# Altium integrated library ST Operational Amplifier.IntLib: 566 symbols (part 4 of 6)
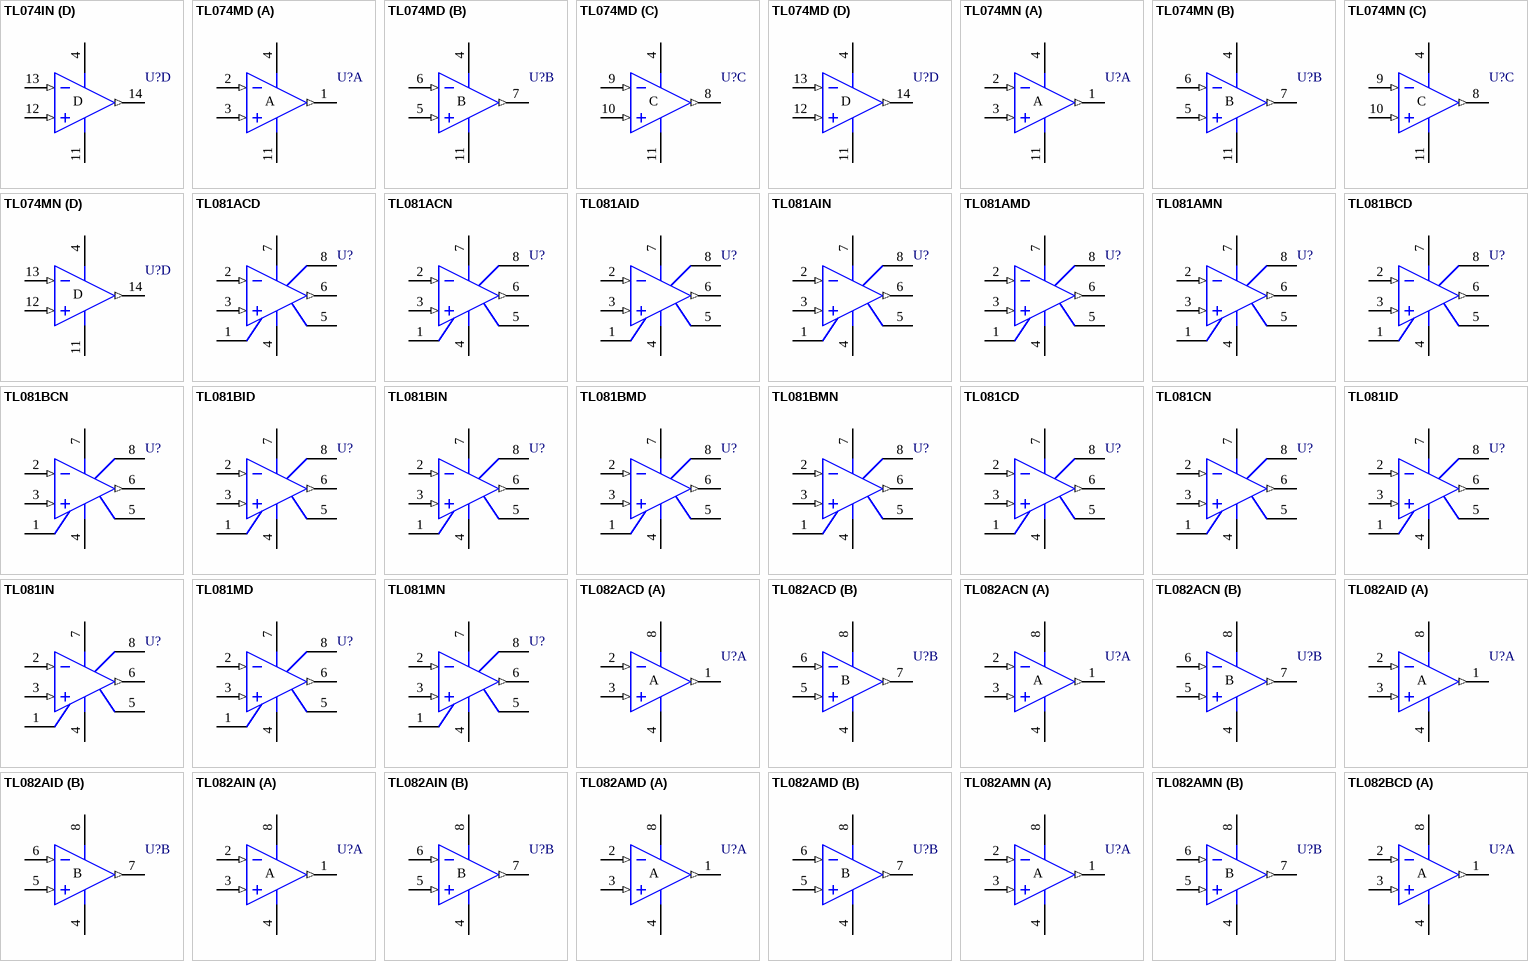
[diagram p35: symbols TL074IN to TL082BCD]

## TL074IN
designator U?
Low-Noise J-FET Quad Operational Amplifier
footprint DIP14 (DIP; 14 Leads; Row Spacing 7.62 mm; Pitch 2.54 mm)
3D model DIP14 (DIP; 14 Leads; Row Spacing 7.62 mm; Pitch 2.54 mm)
simulation model TL074 (SUBCKT)
pins on every part: 4 V+ (power), 11 V- (power)
part A pins: 1 OUT (out), 2 IN- (in), 3 IN+ (in)
part B pins: 5 IN+ (in), 6 IN- (in), 7 OUT (out)
part C pins: 8 OUT (out), 9 IN- (in), 10 IN+ (in)
part D pins: 12 IN+ (in), 13 IN- (in), 14 OUT (out)

## TL074MD
designator U?
Low-Noise J-FET Quad Operational Amplifier
footprint SO14_N (SOIC, 14-Leads, Body 8.7x3.9mm, Pitch 1.27mm, IPC Medium Density)
footprint SO14_L (SOIC, 14-Leads, Body 8.7x3.9mm, Pitch 1.27mm, IPC High Density)
footprint SO14_M (SOIC, 14-Leads, Body 8.7x3.9mm, Pitch 1.27mm, IPC Low Density)
3D model SO14 (14-Pin Small Outline Integrated Circuit 1.27 mm Pitch)
simulation model TL074 (SUBCKT)
pins on every part: 4 V+ (power), 11 V- (power)
part A pins: 1 OUT (out), 2 IN- (in), 3 IN+ (in)
part B pins: 5 IN+ (in), 6 IN- (in), 7 OUT (out)
part C pins: 8 OUT (out), 9 IN- (in), 10 IN+ (in)
part D pins: 12 IN+ (in), 13 IN- (in), 14 OUT (out)

## TL074MN
designator U?
Low-Noise J-FET Quad Operational Amplifier
footprint DIP14 (DIP; 14 Leads; Row Spacing 7.62 mm; Pitch 2.54 mm)
3D model DIP14 (DIP; 14 Leads; Row Spacing 7.62 mm; Pitch 2.54 mm)
simulation model TL074 (SUBCKT)
pins on every part: 4 V+ (power), 11 V- (power)
part A pins: 1 OUT (out), 2 IN- (in), 3 IN+ (in)
part B pins: 5 IN+ (in), 6 IN- (in), 7 OUT (out)
part C pins: 8 OUT (out), 9 IN- (in), 10 IN+ (in)
part D pins: 12 IN+ (in), 13 IN- (in), 14 OUT (out)

## TL081ACD
designator U?
General-Purpose J-FET Single Operational Amplifier
footprint SO8_N (SOIC, 8-Leads, Body 4.9x3.9mm, Pitch 1.27mm, IPC Medium Density)
footprint SO8_L (SOIC, 8-Leads, Body 4.9x3.9mm, Pitch 1.27mm, IPC High Density)
footprint SO8_M (SOIC, 8-Leads, Body 4.9x3.9mm, Pitch 1.27mm, IPC Low Density)
3D model SO8 (8-Pin Small Outline Integrated Circuit 1.27 mm Pitch)
simulation model TL081 (SUBCKT)
pins: 1 OS NULL, 2 IN- (in), 3 IN+ (in), 4 V- (power), 5 OS NULL, 6 OUT (out), 7 V+ (power), 8 NC

## TL081ACN
designator U?
General-Purpose J-FET Single Operational Amplifier
footprint DIP8 (DIP; 8 Leads; Row Spacing 7.62 mm; Pitch 2.54 mm)
3D model DIP8 (DIP; 8 Leads; Row Spacing 7.62 mm; Pitch 2.54 mm)
simulation model TL081 (SUBCKT)
pins: 1 OS NULL, 2 IN- (in), 3 IN+ (in), 4 V- (power), 5 OS NULL, 6 OUT (out), 7 V+ (power), 8 NC

## TL081AID
designator U?
General-Purpose J-FET Single Operational Amplifier
footprint SO8_N (SOIC, 8-Leads, Body 4.9x3.9mm, Pitch 1.27mm, IPC Medium Density)
footprint SO8_L (SOIC, 8-Leads, Body 4.9x3.9mm, Pitch 1.27mm, IPC High Density)
footprint SO8_M (SOIC, 8-Leads, Body 4.9x3.9mm, Pitch 1.27mm, IPC Low Density)
3D model SO8 (8-Pin Small Outline Integrated Circuit 1.27 mm Pitch)
simulation model TL081 (SUBCKT)
pins: 1 OS NULL, 2 IN- (in), 3 IN+ (in), 4 V- (power), 5 OS NULL, 6 OUT (out), 7 V+ (power), 8 NC

## TL081AIN
designator U?
General-Purpose J-FET Single Operational Amplifier
footprint DIP8 (DIP; 8 Leads; Row Spacing 7.62 mm; Pitch 2.54 mm)
3D model DIP8 (DIP; 8 Leads; Row Spacing 7.62 mm; Pitch 2.54 mm)
simulation model TL081 (SUBCKT)
pins: 1 OS NULL, 2 IN- (in), 3 IN+ (in), 4 V- (power), 5 OS NULL, 6 OUT (out), 7 V+ (power), 8 NC

## TL081AMD
designator U?
General-Purpose J-FET Single Operational Amplifier
footprint SO8_N (SOIC, 8-Leads, Body 4.9x3.9mm, Pitch 1.27mm, IPC Medium Density)
footprint SO8_L (SOIC, 8-Leads, Body 4.9x3.9mm, Pitch 1.27mm, IPC High Density)
footprint SO8_M (SOIC, 8-Leads, Body 4.9x3.9mm, Pitch 1.27mm, IPC Low Density)
3D model SO8 (8-Pin Small Outline Integrated Circuit 1.27 mm Pitch)
simulation model TL081 (SUBCKT)
pins: 1 OS NULL, 2 IN- (in), 3 IN+ (in), 4 V- (power), 5 OS NULL, 6 OUT (out), 7 V+ (power), 8 NC

## TL081AMN
designator U?
General-Purpose J-FET Single Operational Amplifier
footprint DIP8 (DIP; 8 Leads; Row Spacing 7.62 mm; Pitch 2.54 mm)
3D model DIP8 (DIP; 8 Leads; Row Spacing 7.62 mm; Pitch 2.54 mm)
simulation model TL081 (SUBCKT)
pins: 1 OS NULL, 2 IN- (in), 3 IN+ (in), 4 V- (power), 5 OS NULL, 6 OUT (out), 7 V+ (power), 8 NC

## TL081BCD
designator U?
General-Purpose J-FET Single Operational Amplifier
footprint SO8_N (SOIC, 8-Leads, Body 4.9x3.9mm, Pitch 1.27mm, IPC Medium Density)
footprint SO8_L (SOIC, 8-Leads, Body 4.9x3.9mm, Pitch 1.27mm, IPC High Density)
footprint SO8_M (SOIC, 8-Leads, Body 4.9x3.9mm, Pitch 1.27mm, IPC Low Density)
3D model SO8 (8-Pin Small Outline Integrated Circuit 1.27 mm Pitch)
simulation model TL081 (SUBCKT)
pins: 1 OS NULL, 2 IN- (in), 3 IN+ (in), 4 V- (power), 5 OS NULL, 6 OUT (out), 7 V+ (power), 8 NC

## TL081BCN
designator U?
General-Purpose J-FET Single Operational Amplifier
footprint DIP8 (DIP; 8 Leads; Row Spacing 7.62 mm; Pitch 2.54 mm)
3D model DIP8 (DIP; 8 Leads; Row Spacing 7.62 mm; Pitch 2.54 mm)
simulation model TL081 (SUBCKT)
pins: 1 OS NULL, 2 IN- (in), 3 IN+ (in), 4 V- (power), 5 OS NULL, 6 OUT (out), 7 V+ (power), 8 NC

## TL081BID
designator U?
General-Purpose J-FET Single Operational Amplifier
footprint SO8_N (SOIC, 8-Leads, Body 4.9x3.9mm, Pitch 1.27mm, IPC Medium Density)
footprint SO8_L (SOIC, 8-Leads, Body 4.9x3.9mm, Pitch 1.27mm, IPC High Density)
footprint SO8_M (SOIC, 8-Leads, Body 4.9x3.9mm, Pitch 1.27mm, IPC Low Density)
3D model SO8 (8-Pin Small Outline Integrated Circuit 1.27 mm Pitch)
simulation model TL081 (SUBCKT)
pins: 1 OS NULL, 2 IN- (in), 3 IN+ (in), 4 V- (power), 5 OS NULL, 6 OUT (out), 7 V+ (power), 8 NC

## TL081BIN
designator U?
General-Purpose J-FET Single Operational Amplifier
footprint DIP8 (DIP; 8 Leads; Row Spacing 7.62 mm; Pitch 2.54 mm)
3D model DIP8 (DIP; 8 Leads; Row Spacing 7.62 mm; Pitch 2.54 mm)
simulation model TL081 (SUBCKT)
pins: 1 OS NULL, 2 IN- (in), 3 IN+ (in), 4 V- (power), 5 OS NULL, 6 OUT (out), 7 V+ (power), 8 NC

## TL081BMD
designator U?
General-Purpose J-FET Single Operational Amplifier
footprint SO8_N (SOIC, 8-Leads, Body 4.9x3.9mm, Pitch 1.27mm, IPC Medium Density)
footprint SO8_L (SOIC, 8-Leads, Body 4.9x3.9mm, Pitch 1.27mm, IPC High Density)
footprint SO8_M (SOIC, 8-Leads, Body 4.9x3.9mm, Pitch 1.27mm, IPC Low Density)
3D model SO8 (8-Pin Small Outline Integrated Circuit 1.27 mm Pitch)
simulation model TL081 (SUBCKT)
pins: 1 OS NULL, 2 IN- (in), 3 IN+ (in), 4 V- (power), 5 OS NULL, 6 OUT (out), 7 V+ (power), 8 NC

## TL081BMN
designator U?
General-Purpose J-FET Single Operational Amplifier
footprint DIP8 (DIP; 8 Leads; Row Spacing 7.62 mm; Pitch 2.54 mm)
3D model DIP8 (DIP; 8 Leads; Row Spacing 7.62 mm; Pitch 2.54 mm)
simulation model TL081 (SUBCKT)
pins: 1 OS NULL, 2 IN- (in), 3 IN+ (in), 4 V- (power), 5 OS NULL, 6 OUT (out), 7 V+ (power), 8 NC

## TL081CD
designator U?
General-Purpose J-FET Single Operational Amplifier
footprint SO8_N (SOIC, 8-Leads, Body 4.9x3.9mm, Pitch 1.27mm, IPC Medium Density)
footprint SO8_L (SOIC, 8-Leads, Body 4.9x3.9mm, Pitch 1.27mm, IPC High Density)
footprint SO8_M (SOIC, 8-Leads, Body 4.9x3.9mm, Pitch 1.27mm, IPC Low Density)
3D model SO8 (8-Pin Small Outline Integrated Circuit 1.27 mm Pitch)
simulation model TL081 (SUBCKT)
pins: 1 OS NULL, 2 IN- (in), 3 IN+ (in), 4 V- (power), 5 OS NULL, 6 OUT (out), 7 V+ (power), 8 NC

## TL081CN
designator U?
General-Purpose J-FET Single Operational Amplifier
footprint DIP8 (DIP; 8 Leads; Row Spacing 7.62 mm; Pitch 2.54 mm)
3D model DIP8 (DIP; 8 Leads; Row Spacing 7.62 mm; Pitch 2.54 mm)
simulation model TL081 (SUBCKT)
pins: 1 OS NULL, 2 IN- (in), 3 IN+ (in), 4 V- (power), 5 OS NULL, 6 OUT (out), 7 V+ (power), 8 NC

## TL081ID
designator U?
General-Purpose J-FET Single Operational Amplifier
footprint SO8_N (SOIC, 8-Leads, Body 4.9x3.9mm, Pitch 1.27mm, IPC Medium Density)
footprint SO8_L (SOIC, 8-Leads, Body 4.9x3.9mm, Pitch 1.27mm, IPC High Density)
footprint SO8_M (SOIC, 8-Leads, Body 4.9x3.9mm, Pitch 1.27mm, IPC Low Density)
3D model SO8 (8-Pin Small Outline Integrated Circuit 1.27 mm Pitch)
simulation model TL081 (SUBCKT)
pins: 1 OS NULL, 2 IN- (in), 3 IN+ (in), 4 V- (power), 5 OS NULL, 6 OUT (out), 7 V+ (power), 8 NC

## TL081IN
designator U?
General-Purpose J-FET Single Operational Amplifier
footprint DIP8 (DIP; 8 Leads; Row Spacing 7.62 mm; Pitch 2.54 mm)
3D model DIP8 (DIP; 8 Leads; Row Spacing 7.62 mm; Pitch 2.54 mm)
simulation model TL081 (SUBCKT)
pins: 1 OS NULL, 2 IN- (in), 3 IN+ (in), 4 V- (power), 5 OS NULL, 6 OUT (out), 7 V+ (power), 8 NC

## TL081MD
designator U?
General-Purpose J-FET Single Operational Amplifier
footprint SO8_N (SOIC, 8-Leads, Body 4.9x3.9mm, Pitch 1.27mm, IPC Medium Density)
footprint SO8_L (SOIC, 8-Leads, Body 4.9x3.9mm, Pitch 1.27mm, IPC High Density)
footprint SO8_M (SOIC, 8-Leads, Body 4.9x3.9mm, Pitch 1.27mm, IPC Low Density)
3D model SO8 (8-Pin Small Outline Integrated Circuit 1.27 mm Pitch)
simulation model TL081 (SUBCKT)
pins: 1 OS NULL, 2 IN- (in), 3 IN+ (in), 4 V- (power), 5 OS NULL, 6 OUT (out), 7 V+ (power), 8 NC

## TL081MN
designator U?
General-Purpose J-FET Single Operational Amplifier
footprint DIP8 (DIP; 8 Leads; Row Spacing 7.62 mm; Pitch 2.54 mm)
3D model DIP8 (DIP; 8 Leads; Row Spacing 7.62 mm; Pitch 2.54 mm)
simulation model TL081 (SUBCKT)
pins: 1 OS NULL, 2 IN- (in), 3 IN+ (in), 4 V- (power), 5 OS NULL, 6 OUT (out), 7 V+ (power), 8 NC

## TL082ACD
designator U?
General-Purpose J-FET Dual Operational Amplifier
footprint SO8_N (SOIC, 8-Leads, Body 4.9x3.9mm, Pitch 1.27mm, IPC Medium Density)
footprint SO8_L (SOIC, 8-Leads, Body 4.9x3.9mm, Pitch 1.27mm, IPC High Density)
footprint SO8_M (SOIC, 8-Leads, Body 4.9x3.9mm, Pitch 1.27mm, IPC Low Density)
3D model SO8 (8-Pin Small Outline Integrated Circuit 1.27 mm Pitch)
simulation model TL082 (SUBCKT)
pins on every part: 4 V- (power), 8 V+ (power)
part A pins: 1 OUT (out), 2 IN- (in), 3 IN+ (in)
part B pins: 5 IN+ (in), 6 IN- (in), 7 OUT (out)

## TL082ACN
designator U?
General-Purpose J-FET Dual Operational Amplifier
footprint DIP8 (DIP; 8 Leads; Row Spacing 7.62 mm; Pitch 2.54 mm)
3D model DIP8 (DIP; 8 Leads; Row Spacing 7.62 mm; Pitch 2.54 mm)
simulation model TL082 (SUBCKT)
pins on every part: 4 V- (power), 8 V+ (power)
part A pins: 1 OUT (out), 2 IN- (in), 3 IN+ (in)
part B pins: 5 IN+ (in), 6 IN- (in), 7 OUT (out)

## TL082AID
designator U?
General-Purpose J-FET Dual Operational Amplifier
footprint SO8_N (SOIC, 8-Leads, Body 4.9x3.9mm, Pitch 1.27mm, IPC Medium Density)
footprint SO8_L (SOIC, 8-Leads, Body 4.9x3.9mm, Pitch 1.27mm, IPC High Density)
footprint SO8_M (SOIC, 8-Leads, Body 4.9x3.9mm, Pitch 1.27mm, IPC Low Density)
3D model SO8 (8-Pin Small Outline Integrated Circuit 1.27 mm Pitch)
simulation model TL082 (SUBCKT)
pins on every part: 4 V- (power), 8 V+ (power)
part A pins: 1 OUT (out), 2 IN- (in), 3 IN+ (in)
part B pins: 5 IN+ (in), 6 IN- (in), 7 OUT (out)

## TL082AIN
designator U?
General-Purpose J-FET Dual Operational Amplifier
footprint DIP8 (DIP; 8 Leads; Row Spacing 7.62 mm; Pitch 2.54 mm)
3D model DIP8 (DIP; 8 Leads; Row Spacing 7.62 mm; Pitch 2.54 mm)
simulation model TL082 (SUBCKT)
pins on every part: 4 V- (power), 8 V+ (power)
part A pins: 1 OUT (out), 2 IN- (in), 3 IN+ (in)
part B pins: 5 IN+ (in), 6 IN- (in), 7 OUT (out)

## TL082AMD
designator U?
General-Purpose J-FET Dual Operational Amplifier
footprint SO8_N (SOIC, 8-Leads, Body 4.9x3.9mm, Pitch 1.27mm, IPC Medium Density)
footprint SO8_L (SOIC, 8-Leads, Body 4.9x3.9mm, Pitch 1.27mm, IPC High Density)
footprint SO8_M (SOIC, 8-Leads, Body 4.9x3.9mm, Pitch 1.27mm, IPC Low Density)
3D model SO8 (8-Pin Small Outline Integrated Circuit 1.27 mm Pitch)
simulation model TL082 (SUBCKT)
pins on every part: 4 V- (power), 8 V+ (power)
part A pins: 1 OUT (out), 2 IN- (in), 3 IN+ (in)
part B pins: 5 IN+ (in), 6 IN- (in), 7 OUT (out)

## TL082AMN
designator U?
General-Purpose J-FET Dual Operational Amplifier
footprint DIP8 (DIP; 8 Leads; Row Spacing 7.62 mm; Pitch 2.54 mm)
3D model DIP8 (DIP; 8 Leads; Row Spacing 7.62 mm; Pitch 2.54 mm)
simulation model TL082 (SUBCKT)
pins on every part: 4 V- (power), 8 V+ (power)
part A pins: 1 OUT (out), 2 IN- (in), 3 IN+ (in)
part B pins: 5 IN+ (in), 6 IN- (in), 7 OUT (out)

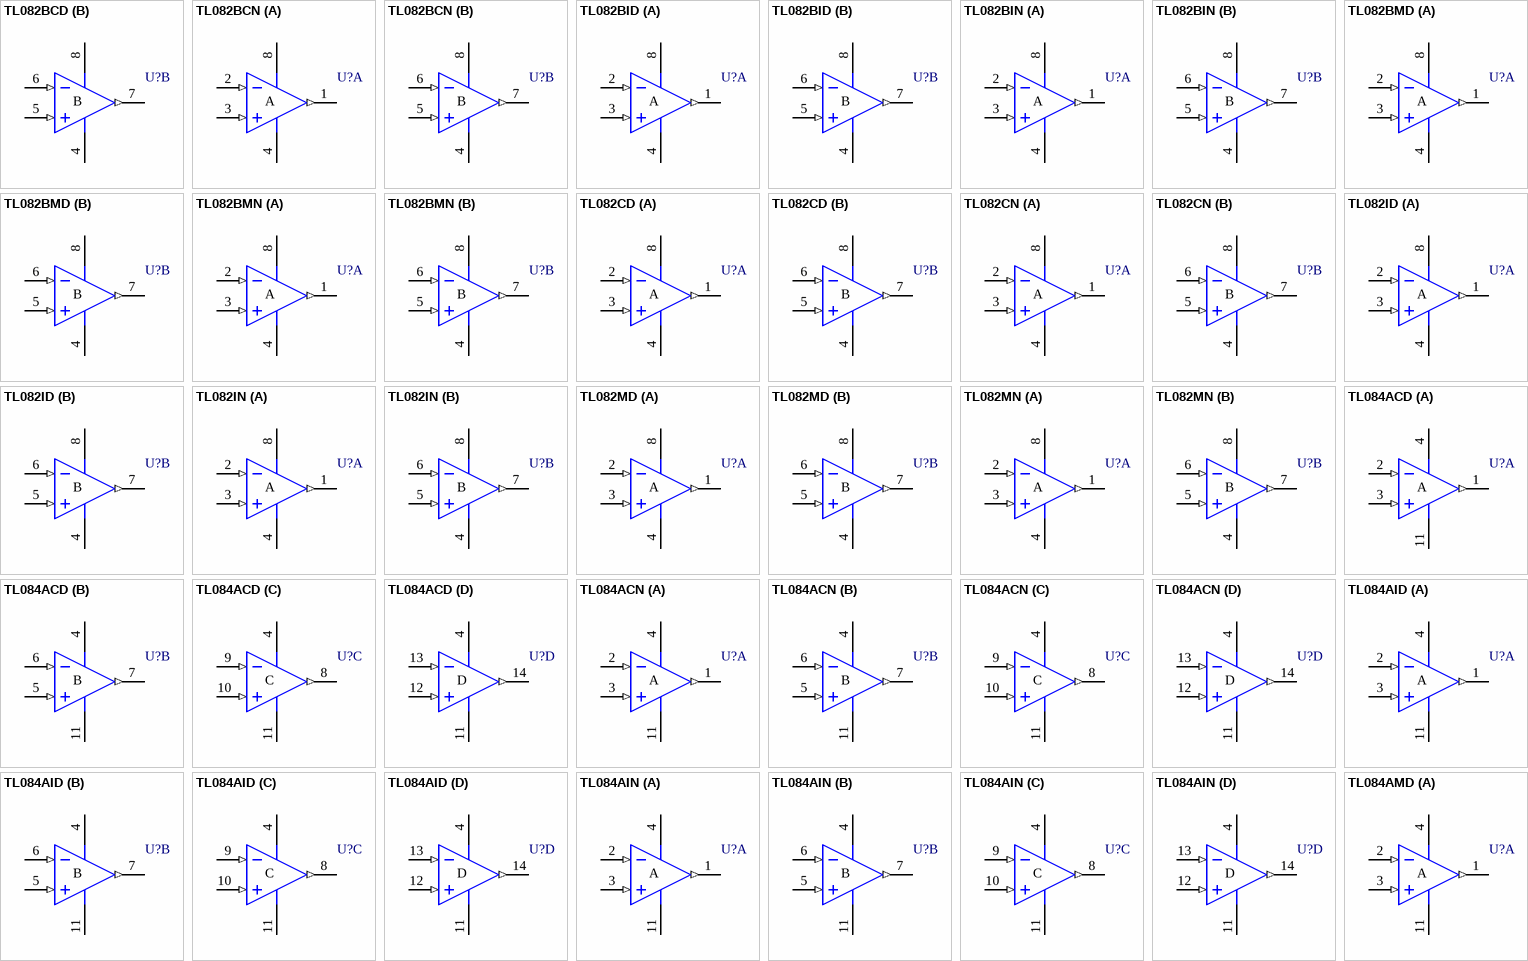
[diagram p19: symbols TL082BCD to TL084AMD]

## TL082BCD
designator U?
General-Purpose J-FET Dual Operational Amplifier
footprint SO8_N (SOIC, 8-Leads, Body 4.9x3.9mm, Pitch 1.27mm, IPC Medium Density)
footprint SO8_L (SOIC, 8-Leads, Body 4.9x3.9mm, Pitch 1.27mm, IPC High Density)
footprint SO8_M (SOIC, 8-Leads, Body 4.9x3.9mm, Pitch 1.27mm, IPC Low Density)
3D model SO8 (8-Pin Small Outline Integrated Circuit 1.27 mm Pitch)
simulation model TL082 (SUBCKT)
pins on every part: 4 V- (power), 8 V+ (power)
part A pins: 1 OUT (out), 2 IN- (in), 3 IN+ (in)
part B pins: 5 IN+ (in), 6 IN- (in), 7 OUT (out)

## TL082BCN
designator U?
General-Purpose J-FET Dual Operational Amplifier
footprint DIP8 (DIP; 8 Leads; Row Spacing 7.62 mm; Pitch 2.54 mm)
3D model DIP8 (DIP; 8 Leads; Row Spacing 7.62 mm; Pitch 2.54 mm)
simulation model TL082 (SUBCKT)
pins on every part: 4 V- (power), 8 V+ (power)
part A pins: 1 OUT (out), 2 IN- (in), 3 IN+ (in)
part B pins: 5 IN+ (in), 6 IN- (in), 7 OUT (out)

## TL082BID
designator U?
General-Purpose J-FET Dual Operational Amplifier
footprint SO8_N (SOIC, 8-Leads, Body 4.9x3.9mm, Pitch 1.27mm, IPC Medium Density)
footprint SO8_L (SOIC, 8-Leads, Body 4.9x3.9mm, Pitch 1.27mm, IPC High Density)
footprint SO8_M (SOIC, 8-Leads, Body 4.9x3.9mm, Pitch 1.27mm, IPC Low Density)
3D model SO8 (8-Pin Small Outline Integrated Circuit 1.27 mm Pitch)
simulation model TL082 (SUBCKT)
pins on every part: 4 V- (power), 8 V+ (power)
part A pins: 1 OUT (out), 2 IN- (in), 3 IN+ (in)
part B pins: 5 IN+ (in), 6 IN- (in), 7 OUT (out)

## TL082BIN
designator U?
General-Purpose J-FET Dual Operational Amplifier
footprint DIP8 (DIP; 8 Leads; Row Spacing 7.62 mm; Pitch 2.54 mm)
3D model DIP8 (DIP; 8 Leads; Row Spacing 7.62 mm; Pitch 2.54 mm)
simulation model TL082 (SUBCKT)
pins on every part: 4 V- (power), 8 V+ (power)
part A pins: 1 OUT (out), 2 IN- (in), 3 IN+ (in)
part B pins: 5 IN+ (in), 6 IN- (in), 7 OUT (out)

## TL082BMD
designator U?
General-Purpose J-FET Dual Operational Amplifier
footprint SO8_N (SOIC, 8-Leads, Body 4.9x3.9mm, Pitch 1.27mm, IPC Medium Density)
footprint SO8_L (SOIC, 8-Leads, Body 4.9x3.9mm, Pitch 1.27mm, IPC High Density)
footprint SO8_M (SOIC, 8-Leads, Body 4.9x3.9mm, Pitch 1.27mm, IPC Low Density)
3D model SO8 (8-Pin Small Outline Integrated Circuit 1.27 mm Pitch)
simulation model TL082 (SUBCKT)
pins on every part: 4 V- (power), 8 V+ (power)
part A pins: 1 OUT (out), 2 IN- (in), 3 IN+ (in)
part B pins: 5 IN+ (in), 6 IN- (in), 7 OUT (out)

## TL082BMN
designator U?
General-Purpose J-FET Dual Operational Amplifier
footprint DIP8 (DIP; 8 Leads; Row Spacing 7.62 mm; Pitch 2.54 mm)
3D model DIP8 (DIP; 8 Leads; Row Spacing 7.62 mm; Pitch 2.54 mm)
simulation model TL082 (SUBCKT)
pins on every part: 4 V- (power), 8 V+ (power)
part A pins: 1 OUT (out), 2 IN- (in), 3 IN+ (in)
part B pins: 5 IN+ (in), 6 IN- (in), 7 OUT (out)

## TL082CD
designator U?
General-Purpose J-FET Dual Operational Amplifier
footprint SO8_N (SOIC, 8-Leads, Body 4.9x3.9mm, Pitch 1.27mm, IPC Medium Density)
footprint SO8_L (SOIC, 8-Leads, Body 4.9x3.9mm, Pitch 1.27mm, IPC High Density)
footprint SO8_M (SOIC, 8-Leads, Body 4.9x3.9mm, Pitch 1.27mm, IPC Low Density)
3D model SO8 (8-Pin Small Outline Integrated Circuit 1.27 mm Pitch)
simulation model TL082 (SUBCKT)
pins on every part: 4 V- (power), 8 V+ (power)
part A pins: 1 OUT (out), 2 IN- (in), 3 IN+ (in)
part B pins: 5 IN+ (in), 6 IN- (in), 7 OUT (out)

## TL082CN
designator U?
General-Purpose J-FET Dual Operational Amplifier
footprint DIP8 (DIP; 8 Leads; Row Spacing 7.62 mm; Pitch 2.54 mm)
3D model DIP8 (DIP; 8 Leads; Row Spacing 7.62 mm; Pitch 2.54 mm)
simulation model TL082 (SUBCKT)
pins on every part: 4 V- (power), 8 V+ (power)
part A pins: 1 OUT (out), 2 IN- (in), 3 IN+ (in)
part B pins: 5 IN+ (in), 6 IN- (in), 7 OUT (out)

## TL082ID
designator U?
General-Purpose J-FET Dual Operational Amplifier
footprint SO8_N (SOIC, 8-Leads, Body 4.9x3.9mm, Pitch 1.27mm, IPC Medium Density)
footprint SO8_L (SOIC, 8-Leads, Body 4.9x3.9mm, Pitch 1.27mm, IPC High Density)
footprint SO8_M (SOIC, 8-Leads, Body 4.9x3.9mm, Pitch 1.27mm, IPC Low Density)
3D model SO8 (8-Pin Small Outline Integrated Circuit 1.27 mm Pitch)
simulation model TL082 (SUBCKT)
pins on every part: 4 V- (power), 8 V+ (power)
part A pins: 1 OUT (out), 2 IN- (in), 3 IN+ (in)
part B pins: 5 IN+ (in), 6 IN- (in), 7 OUT (out)

## TL082IN
designator U?
General-Purpose J-FET Dual Operational Amplifier
footprint DIP8 (DIP; 8 Leads; Row Spacing 7.62 mm; Pitch 2.54 mm)
3D model DIP8 (DIP; 8 Leads; Row Spacing 7.62 mm; Pitch 2.54 mm)
simulation model TL082 (SUBCKT)
pins on every part: 4 V- (power), 8 V+ (power)
part A pins: 1 OUT (out), 2 IN- (in), 3 IN+ (in)
part B pins: 5 IN+ (in), 6 IN- (in), 7 OUT (out)

## TL082MD
designator U?
General-Purpose J-FET Dual Operational Amplifier
footprint SO8_N (SOIC, 8-Leads, Body 4.9x3.9mm, Pitch 1.27mm, IPC Medium Density)
footprint SO8_L (SOIC, 8-Leads, Body 4.9x3.9mm, Pitch 1.27mm, IPC High Density)
footprint SO8_M (SOIC, 8-Leads, Body 4.9x3.9mm, Pitch 1.27mm, IPC Low Density)
3D model SO8 (8-Pin Small Outline Integrated Circuit 1.27 mm Pitch)
simulation model TL082 (SUBCKT)
pins on every part: 4 V- (power), 8 V+ (power)
part A pins: 1 OUT (out), 2 IN- (in), 3 IN+ (in)
part B pins: 5 IN+ (in), 6 IN- (in), 7 OUT (out)

## TL082MN
designator U?
General-Purpose J-FET Dual Operational Amplifier
footprint DIP8 (DIP; 8 Leads; Row Spacing 7.62 mm; Pitch 2.54 mm)
3D model DIP8 (DIP; 8 Leads; Row Spacing 7.62 mm; Pitch 2.54 mm)
simulation model TL082 (SUBCKT)
pins on every part: 4 V- (power), 8 V+ (power)
part A pins: 1 OUT (out), 2 IN- (in), 3 IN+ (in)
part B pins: 5 IN+ (in), 6 IN- (in), 7 OUT (out)

## TL084ACD
designator U?
General-Purpose J-FET Quad Operational Amplifier
footprint SO14_N (SOIC, 14-Leads, Body 8.7x3.9mm, Pitch 1.27mm, IPC Medium Density)
footprint SO14_L (SOIC, 14-Leads, Body 8.7x3.9mm, Pitch 1.27mm, IPC High Density)
footprint SO14_M (SOIC, 14-Leads, Body 8.7x3.9mm, Pitch 1.27mm, IPC Low Density)
3D model SO14 (14-Pin Small Outline Integrated Circuit 1.27 mm Pitch)
simulation model TL084 (SUBCKT)
pins on every part: 4 V+ (power), 11 V- (power)
part A pins: 1 OUT (out), 2 IN- (in), 3 IN+ (in)
part B pins: 5 IN+ (in), 6 IN- (in), 7 OUT (out)
part C pins: 8 OUT (out), 9 IN- (in), 10 IN+ (in)
part D pins: 12 IN+ (in), 13 IN- (in), 14 OUT (out)

## TL084ACN
designator U?
General-Purpose J-FET Quad Operational Amplifier
footprint DIP14 (DIP; 14 Leads; Row Spacing 7.62 mm; Pitch 2.54 mm)
3D model DIP14 (DIP; 14 Leads; Row Spacing 7.62 mm; Pitch 2.54 mm)
simulation model TL084 (SUBCKT)
pins on every part: 4 V+ (power), 11 V- (power)
part A pins: 1 OUT (out), 2 IN- (in), 3 IN+ (in)
part B pins: 5 IN+ (in), 6 IN- (in), 7 OUT (out)
part C pins: 8 OUT (out), 9 IN- (in), 10 IN+ (in)
part D pins: 12 IN+ (in), 13 IN- (in), 14 OUT (out)

## TL084AID
designator U?
General-Purpose J-FET Quad Operational Amplifier
footprint SO14_N (SOIC, 14-Leads, Body 8.7x3.9mm, Pitch 1.27mm, IPC Medium Density)
footprint SO14_L (SOIC, 14-Leads, Body 8.7x3.9mm, Pitch 1.27mm, IPC High Density)
footprint SO14_M (SOIC, 14-Leads, Body 8.7x3.9mm, Pitch 1.27mm, IPC Low Density)
3D model SO14 (14-Pin Small Outline Integrated Circuit 1.27 mm Pitch)
simulation model TL084 (SUBCKT)
pins on every part: 4 V+ (power), 11 V- (power)
part A pins: 1 OUT (out), 2 IN- (in), 3 IN+ (in)
part B pins: 5 IN+ (in), 6 IN- (in), 7 OUT (out)
part C pins: 8 OUT (out), 9 IN- (in), 10 IN+ (in)
part D pins: 12 IN+ (in), 13 IN- (in), 14 OUT (out)

## TL084AIN
designator U?
General-Purpose J-FET Quad Operational Amplifier
footprint DIP14 (DIP; 14 Leads; Row Spacing 7.62 mm; Pitch 2.54 mm)
3D model DIP14 (DIP; 14 Leads; Row Spacing 7.62 mm; Pitch 2.54 mm)
simulation model TL084 (SUBCKT)
pins on every part: 4 V+ (power), 11 V- (power)
part A pins: 1 OUT (out), 2 IN- (in), 3 IN+ (in)
part B pins: 5 IN+ (in), 6 IN- (in), 7 OUT (out)
part C pins: 8 OUT (out), 9 IN- (in), 10 IN+ (in)
part D pins: 12 IN+ (in), 13 IN- (in), 14 OUT (out)

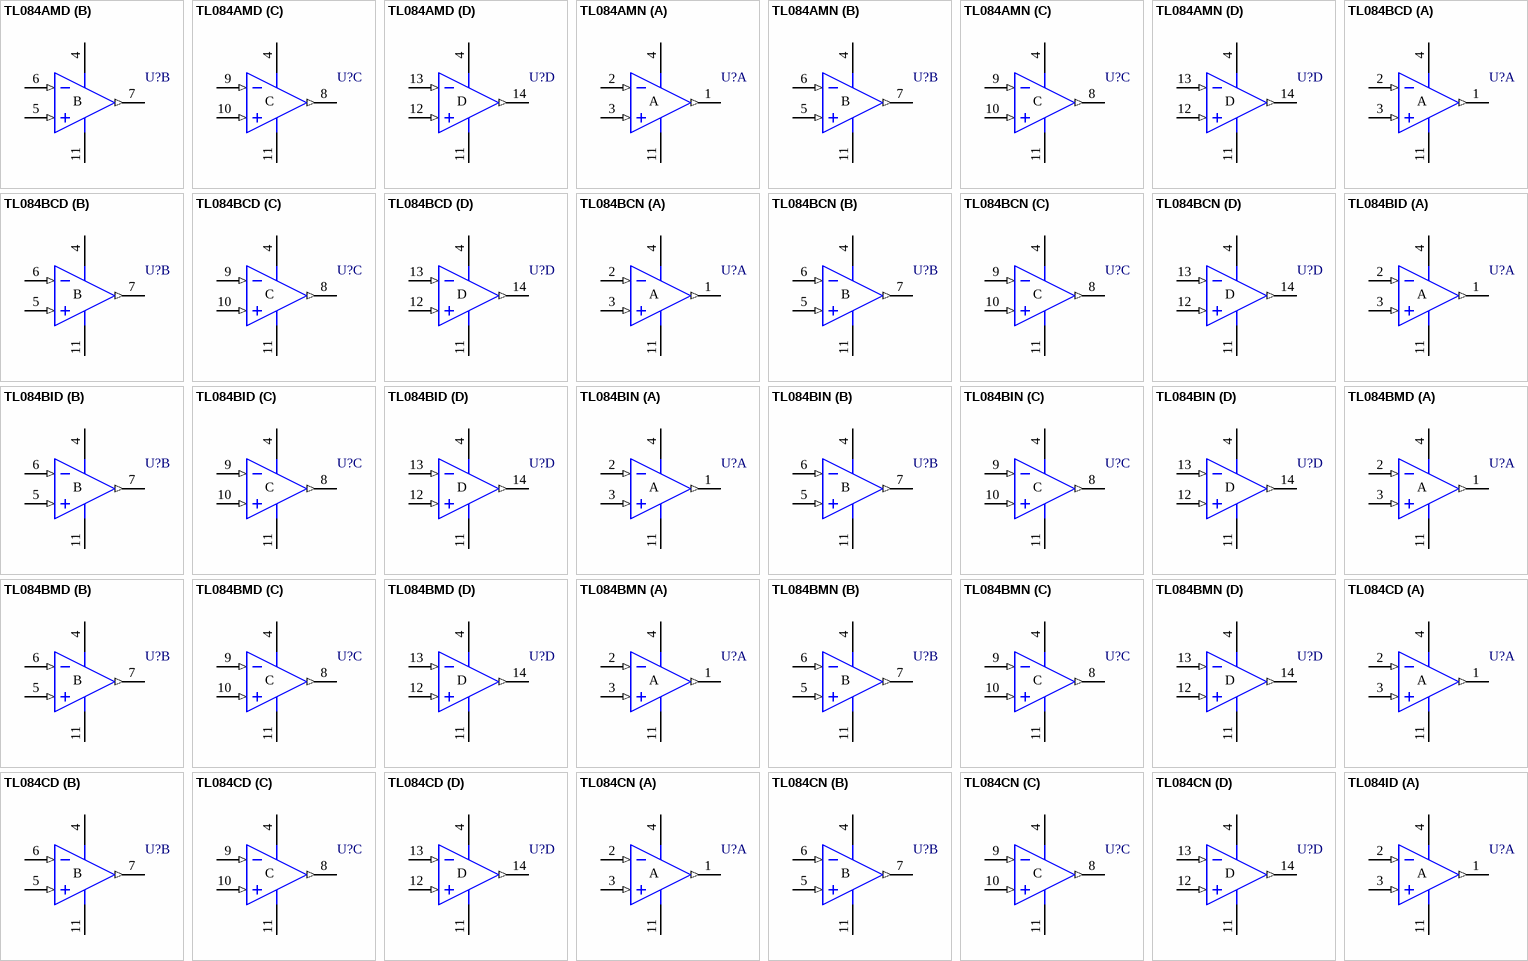
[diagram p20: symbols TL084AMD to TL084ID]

## TL084AMD
designator U?
General-Purpose J-FET Quad Operational Amplifier
footprint SO14_N (SOIC, 14-Leads, Body 8.7x3.9mm, Pitch 1.27mm, IPC Medium Density)
footprint SO14_L (SOIC, 14-Leads, Body 8.7x3.9mm, Pitch 1.27mm, IPC High Density)
footprint SO14_M (SOIC, 14-Leads, Body 8.7x3.9mm, Pitch 1.27mm, IPC Low Density)
3D model SO14 (14-Pin Small Outline Integrated Circuit 1.27 mm Pitch)
simulation model TL084 (SUBCKT)
pins on every part: 4 V+ (power), 11 V- (power)
part A pins: 1 OUT (out), 2 IN- (in), 3 IN+ (in)
part B pins: 5 IN+ (in), 6 IN- (in), 7 OUT (out)
part C pins: 8 OUT (out), 9 IN- (in), 10 IN+ (in)
part D pins: 12 IN+ (in), 13 IN- (in), 14 OUT (out)

## TL084AMN
designator U?
General-Purpose J-FET Quad Operational Amplifier
footprint DIP14 (DIP; 14 Leads; Row Spacing 7.62 mm; Pitch 2.54 mm)
3D model DIP14 (DIP; 14 Leads; Row Spacing 7.62 mm; Pitch 2.54 mm)
simulation model TL084 (SUBCKT)
pins on every part: 4 V+ (power), 11 V- (power)
part A pins: 1 OUT (out), 2 IN- (in), 3 IN+ (in)
part B pins: 5 IN+ (in), 6 IN- (in), 7 OUT (out)
part C pins: 8 OUT (out), 9 IN- (in), 10 IN+ (in)
part D pins: 12 IN+ (in), 13 IN- (in), 14 OUT (out)

## TL084BCD
designator U?
General-Purpose J-FET Quad Operational Amplifier
footprint SO14_N (SOIC, 14-Leads, Body 8.7x3.9mm, Pitch 1.27mm, IPC Medium Density)
footprint SO14_L (SOIC, 14-Leads, Body 8.7x3.9mm, Pitch 1.27mm, IPC High Density)
footprint SO14_M (SOIC, 14-Leads, Body 8.7x3.9mm, Pitch 1.27mm, IPC Low Density)
3D model SO14 (14-Pin Small Outline Integrated Circuit 1.27 mm Pitch)
simulation model TL084 (SUBCKT)
pins on every part: 4 V+ (power), 11 V- (power)
part A pins: 1 OUT (out), 2 IN- (in), 3 IN+ (in)
part B pins: 5 IN+ (in), 6 IN- (in), 7 OUT (out)
part C pins: 8 OUT (out), 9 IN- (in), 10 IN+ (in)
part D pins: 12 IN+ (in), 13 IN- (in), 14 OUT (out)

## TL084BCN
designator U?
General-Purpose J-FET Quad Operational Amplifier
footprint DIP14 (DIP; 14 Leads; Row Spacing 7.62 mm; Pitch 2.54 mm)
3D model DIP14 (DIP; 14 Leads; Row Spacing 7.62 mm; Pitch 2.54 mm)
simulation model TL084 (SUBCKT)
pins on every part: 4 V+ (power), 11 V- (power)
part A pins: 1 OUT (out), 2 IN- (in), 3 IN+ (in)
part B pins: 5 IN+ (in), 6 IN- (in), 7 OUT (out)
part C pins: 8 OUT (out), 9 IN- (in), 10 IN+ (in)
part D pins: 12 IN+ (in), 13 IN- (in), 14 OUT (out)

## TL084BID
designator U?
General-Purpose J-FET Quad Operational Amplifier
footprint SO14_N (SOIC, 14-Leads, Body 8.7x3.9mm, Pitch 1.27mm, IPC Medium Density)
footprint SO14_L (SOIC, 14-Leads, Body 8.7x3.9mm, Pitch 1.27mm, IPC High Density)
footprint SO14_M (SOIC, 14-Leads, Body 8.7x3.9mm, Pitch 1.27mm, IPC Low Density)
3D model SO14 (14-Pin Small Outline Integrated Circuit 1.27 mm Pitch)
simulation model TL084 (SUBCKT)
pins on every part: 4 V+ (power), 11 V- (power)
part A pins: 1 OUT (out), 2 IN- (in), 3 IN+ (in)
part B pins: 5 IN+ (in), 6 IN- (in), 7 OUT (out)
part C pins: 8 OUT (out), 9 IN- (in), 10 IN+ (in)
part D pins: 12 IN+ (in), 13 IN- (in), 14 OUT (out)

## TL084BIN
designator U?
General-Purpose J-FET Quad Operational Amplifier
footprint DIP14 (DIP; 14 Leads; Row Spacing 7.62 mm; Pitch 2.54 mm)
3D model DIP14 (DIP; 14 Leads; Row Spacing 7.62 mm; Pitch 2.54 mm)
simulation model TL084 (SUBCKT)
pins on every part: 4 V+ (power), 11 V- (power)
part A pins: 1 OUT (out), 2 IN- (in), 3 IN+ (in)
part B pins: 5 IN+ (in), 6 IN- (in), 7 OUT (out)
part C pins: 8 OUT (out), 9 IN- (in), 10 IN+ (in)
part D pins: 12 IN+ (in), 13 IN- (in), 14 OUT (out)

## TL084BMD
designator U?
General-Purpose J-FET Quad Operational Amplifier
footprint SO14_N (SOIC, 14-Leads, Body 8.7x3.9mm, Pitch 1.27mm, IPC Medium Density)
footprint SO14_L (SOIC, 14-Leads, Body 8.7x3.9mm, Pitch 1.27mm, IPC High Density)
footprint SO14_M (SOIC, 14-Leads, Body 8.7x3.9mm, Pitch 1.27mm, IPC Low Density)
3D model SO14 (14-Pin Small Outline Integrated Circuit 1.27 mm Pitch)
simulation model TL084 (SUBCKT)
pins on every part: 4 V+ (power), 11 V- (power)
part A pins: 1 OUT (out), 2 IN- (in), 3 IN+ (in)
part B pins: 5 IN+ (in), 6 IN- (in), 7 OUT (out)
part C pins: 8 OUT (out), 9 IN- (in), 10 IN+ (in)
part D pins: 12 IN+ (in), 13 IN- (in), 14 OUT (out)

## TL084BMN
designator U?
General-Purpose J-FET Quad Operational Amplifier
footprint DIP14 (DIP; 14 Leads; Row Spacing 7.62 mm; Pitch 2.54 mm)
3D model DIP14 (DIP; 14 Leads; Row Spacing 7.62 mm; Pitch 2.54 mm)
simulation model TL084 (SUBCKT)
pins on every part: 4 V+ (power), 11 V- (power)
part A pins: 1 OUT (out), 2 IN- (in), 3 IN+ (in)
part B pins: 5 IN+ (in), 6 IN- (in), 7 OUT (out)
part C pins: 8 OUT (out), 9 IN- (in), 10 IN+ (in)
part D pins: 12 IN+ (in), 13 IN- (in), 14 OUT (out)

## TL084CD
designator U?
General-Purpose J-FET Quad Operational Amplifier
footprint SO14_N (SOIC, 14-Leads, Body 8.7x3.9mm, Pitch 1.27mm, IPC Medium Density)
footprint SO14_L (SOIC, 14-Leads, Body 8.7x3.9mm, Pitch 1.27mm, IPC High Density)
footprint SO14_M (SOIC, 14-Leads, Body 8.7x3.9mm, Pitch 1.27mm, IPC Low Density)
3D model SO14 (14-Pin Small Outline Integrated Circuit 1.27 mm Pitch)
simulation model TL084 (SUBCKT)
pins on every part: 4 V+ (power), 11 V- (power)
part A pins: 1 OUT (out), 2 IN- (in), 3 IN+ (in)
part B pins: 5 IN+ (in), 6 IN- (in), 7 OUT (out)
part C pins: 8 OUT (out), 9 IN- (in), 10 IN+ (in)
part D pins: 12 IN+ (in), 13 IN- (in), 14 OUT (out)

## TL084CN
designator U?
General-Purpose J-FET Quad Operational Amplifier
footprint DIP14 (DIP; 14 Leads; Row Spacing 7.62 mm; Pitch 2.54 mm)
3D model DIP14 (DIP; 14 Leads; Row Spacing 7.62 mm; Pitch 2.54 mm)
simulation model TL084 (SUBCKT)
pins on every part: 4 V+ (power), 11 V- (power)
part A pins: 1 OUT (out), 2 IN- (in), 3 IN+ (in)
part B pins: 5 IN+ (in), 6 IN- (in), 7 OUT (out)
part C pins: 8 OUT (out), 9 IN- (in), 10 IN+ (in)
part D pins: 12 IN+ (in), 13 IN- (in), 14 OUT (out)

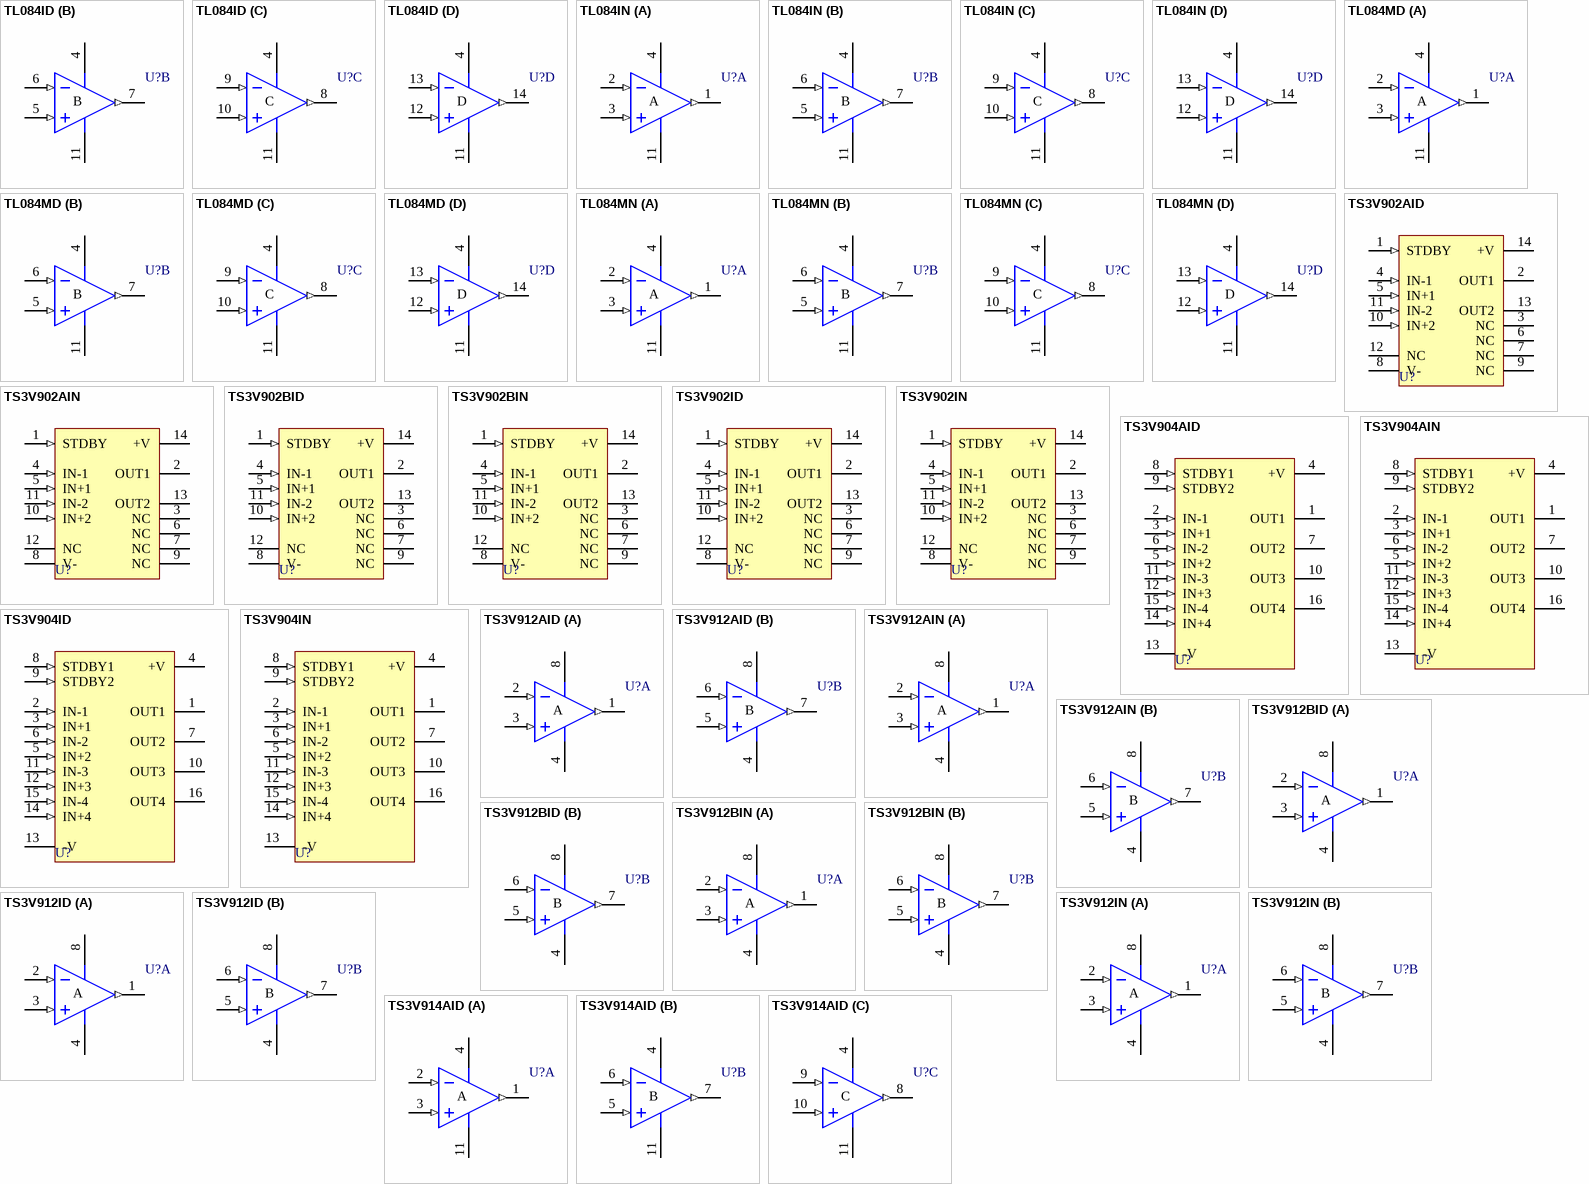
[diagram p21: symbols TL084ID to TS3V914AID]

## TL084ID
designator U?
General-Purpose J-FET Quad Operational Amplifier
footprint SO14_N (SOIC, 14-Leads, Body 8.7x3.9mm, Pitch 1.27mm, IPC Medium Density)
footprint SO14_L (SOIC, 14-Leads, Body 8.7x3.9mm, Pitch 1.27mm, IPC High Density)
footprint SO14_M (SOIC, 14-Leads, Body 8.7x3.9mm, Pitch 1.27mm, IPC Low Density)
3D model SO14 (14-Pin Small Outline Integrated Circuit 1.27 mm Pitch)
simulation model TL084 (SUBCKT)
pins on every part: 4 V+ (power), 11 V- (power)
part A pins: 1 OUT (out), 2 IN- (in), 3 IN+ (in)
part B pins: 5 IN+ (in), 6 IN- (in), 7 OUT (out)
part C pins: 8 OUT (out), 9 IN- (in), 10 IN+ (in)
part D pins: 12 IN+ (in), 13 IN- (in), 14 OUT (out)

## TL084IN
designator U?
General-Purpose J-FET Quad Operational Amplifier
footprint DIP14 (DIP; 14 Leads; Row Spacing 7.62 mm; Pitch 2.54 mm)
3D model DIP14 (DIP; 14 Leads; Row Spacing 7.62 mm; Pitch 2.54 mm)
simulation model TL084 (SUBCKT)
pins on every part: 4 V+ (power), 11 V- (power)
part A pins: 1 OUT (out), 2 IN- (in), 3 IN+ (in)
part B pins: 5 IN+ (in), 6 IN- (in), 7 OUT (out)
part C pins: 8 OUT (out), 9 IN- (in), 10 IN+ (in)
part D pins: 12 IN+ (in), 13 IN- (in), 14 OUT (out)

## TL084MD
designator U?
General-Purpose J-FET Quad Operational Amplifier
footprint SO14_N (SOIC, 14-Leads, Body 8.7x3.9mm, Pitch 1.27mm, IPC Medium Density)
footprint SO14_L (SOIC, 14-Leads, Body 8.7x3.9mm, Pitch 1.27mm, IPC High Density)
footprint SO14_M (SOIC, 14-Leads, Body 8.7x3.9mm, Pitch 1.27mm, IPC Low Density)
3D model SO14 (14-Pin Small Outline Integrated Circuit 1.27 mm Pitch)
simulation model TL084 (SUBCKT)
pins on every part: 4 V+ (power), 11 V- (power)
part A pins: 1 OUT (out), 2 IN- (in), 3 IN+ (in)
part B pins: 5 IN+ (in), 6 IN- (in), 7 OUT (out)
part C pins: 8 OUT (out), 9 IN- (in), 10 IN+ (in)
part D pins: 12 IN+ (in), 13 IN- (in), 14 OUT (out)

## TL084MN
designator U?
General-Purpose J-FET Quad Operational Amplifier
footprint DIP14 (DIP; 14 Leads; Row Spacing 7.62 mm; Pitch 2.54 mm)
3D model DIP14 (DIP; 14 Leads; Row Spacing 7.62 mm; Pitch 2.54 mm)
simulation model TL084 (SUBCKT)
pins on every part: 4 V+ (power), 11 V- (power)
part A pins: 1 OUT (out), 2 IN- (in), 3 IN+ (in)
part B pins: 5 IN+ (in), 6 IN- (in), 7 OUT (out)
part C pins: 8 OUT (out), 9 IN- (in), 10 IN+ (in)
part D pins: 12 IN+ (in), 13 IN- (in), 14 OUT (out)

## TS3V902AID
designator U?
3V Rail-to-Rail CMOS Dual Operational Amplifier (with Standby Position)
footprint SO14_N (SOIC, 14-Leads, Body 8.7x3.9mm, Pitch 1.27mm, IPC Medium Density)
footprint SO14_L (SOIC, 14-Leads, Body 8.7x3.9mm, Pitch 1.27mm, IPC High Density)
footprint SO14_M (SOIC, 14-Leads, Body 8.7x3.9mm, Pitch 1.27mm, IPC Low Density)
3D model SO14 (14-Pin Small Outline Integrated Circuit 1.27 mm Pitch)
pins: 1 STDBY (in), 2 OUT1 (hiz), 3 NC, 4 IN-1 (in), 5 IN+1 (in), 6 NC, 7 NC, 8 V- (power), 9 NC, 10 IN+2 (in), 11 IN-2 (in), 12 NC, 13 OUT2 (hiz), 14 +V (power)

## TS3V902AIN
designator U?
3V Rail-to-Rail CMOS Dual Operational Amplifier (with Standby Position)
footprint DIP14 (DIP; 14 Leads; Row Spacing 7.62 mm; Pitch 2.54 mm)
3D model DIP14 (DIP; 14 Leads; Row Spacing 7.62 mm; Pitch 2.54 mm)
pins: 1 STDBY (in), 2 OUT1 (hiz), 3 NC, 4 IN-1 (in), 5 IN+1 (in), 6 NC, 7 NC, 8 V- (power), 9 NC, 10 IN+2 (in), 11 IN-2 (in), 12 NC, 13 OUT2 (hiz), 14 +V (power)

## TS3V902BID
designator U?
3V Rail-to-Rail CMOS Dual Operational Amplifier (with Standby Position)
footprint SO14_N (SOIC, 14-Leads, Body 8.7x3.9mm, Pitch 1.27mm, IPC Medium Density)
footprint SO14_L (SOIC, 14-Leads, Body 8.7x3.9mm, Pitch 1.27mm, IPC High Density)
footprint SO14_M (SOIC, 14-Leads, Body 8.7x3.9mm, Pitch 1.27mm, IPC Low Density)
3D model SO14 (14-Pin Small Outline Integrated Circuit 1.27 mm Pitch)
pins: 1 STDBY (in), 2 OUT1 (hiz), 3 NC, 4 IN-1 (in), 5 IN+1 (in), 6 NC, 7 NC, 8 V- (power), 9 NC, 10 IN+2 (in), 11 IN-2 (in), 12 NC, 13 OUT2 (hiz), 14 +V (power)

## TS3V902BIN
designator U?
3V Rail-to-Rail CMOS Dual Operational Amplifier (with Standby Position)
footprint DIP14 (DIP; 14 Leads; Row Spacing 7.62 mm; Pitch 2.54 mm)
3D model DIP14 (DIP; 14 Leads; Row Spacing 7.62 mm; Pitch 2.54 mm)
pins: 1 STDBY (in), 2 OUT1 (hiz), 3 NC, 4 IN-1 (in), 5 IN+1 (in), 6 NC, 7 NC, 8 V- (power), 9 NC, 10 IN+2 (in), 11 IN-2 (in), 12 NC, 13 OUT2 (hiz), 14 +V (power)

## TS3V902ID
designator U?
3V Rail-to-Rail CMOS Dual Operational Amplifier (with Standby Position)
footprint SO14_N (SOIC, 14-Leads, Body 8.7x3.9mm, Pitch 1.27mm, IPC Medium Density)
footprint SO14_L (SOIC, 14-Leads, Body 8.7x3.9mm, Pitch 1.27mm, IPC High Density)
footprint SO14_M (SOIC, 14-Leads, Body 8.7x3.9mm, Pitch 1.27mm, IPC Low Density)
3D model SO14 (14-Pin Small Outline Integrated Circuit 1.27 mm Pitch)
pins: 1 STDBY (in), 2 OUT1 (hiz), 3 NC, 4 IN-1 (in), 5 IN+1 (in), 6 NC, 7 NC, 8 V- (power), 9 NC, 10 IN+2 (in), 11 IN-2 (in), 12 NC, 13 OUT2 (hiz), 14 +V (power)

## TS3V902IN
designator U?
3V Rail-to-Rail CMOS Dual Operational Amplifier (with Standby Position)
footprint DIP14 (DIP; 14 Leads; Row Spacing 7.62 mm; Pitch 2.54 mm)
3D model DIP14 (DIP; 14 Leads; Row Spacing 7.62 mm; Pitch 2.54 mm)
pins: 1 STDBY (in), 2 OUT1 (hiz), 3 NC, 4 IN-1 (in), 5 IN+1 (in), 6 NC, 7 NC, 8 V- (power), 9 NC, 10 IN+2 (in), 11 IN-2 (in), 12 NC, 13 OUT2 (hiz), 14 +V (power)

## TS3V904AID
designator U?
3V Rail-to-Rail CMOS Quad Operational Amplifier (with Standby Position)
footprint SO16_N (SOIC, 16-Leads, Body 9.9x3.9mm, Pitch 1.27mm, IPC Medium Density)
footprint SO16_L (SOIC, 16-Leads, Body 9.9x3.9mm, Pitch 1.27mm, IPC High Density)
footprint SO16_M (SOIC, 16-Leads, Body 9.9x3.9mm, Pitch 1.27mm, IPC Low Density)
3D model SO16 (16-Pin Small Outline Integrated Circuit 1.27 mm Pitch)
pins: 1 OUT1 (hiz), 2 IN-1 (in), 3 IN+1 (in), 4 +V (power), 5 IN+2 (in), 6 IN-2 (in), 7 OUT2 (hiz), 8 STDBY1 (in), 9 STDBY2 (in), 10 OUT3 (hiz), 11 IN-3 (in), 12 IN+3 (in), 13 -V (power), 14 IN+4 (in), 15 IN-4 (in), 16 OUT4 (hiz)

## TS3V904AIN
designator U?
3V Rail-to-Rail CMOS Quad Operational Amplifier (with Standby Position)
footprint DIP16 (DIP; 16 Leads; Row Spacing 7.62 mm; Pitch 2.54 mm)
3D model DIP16 (DIP; 16 Leads; Row Spacing 7.62 mm; Pitch 2.54 mm)
pins: 1 OUT1 (hiz), 2 IN-1 (in), 3 IN+1 (in), 4 +V (power), 5 IN+2 (in), 6 IN-2 (in), 7 OUT2 (hiz), 8 STDBY1 (in), 9 STDBY2 (in), 10 OUT3 (hiz), 11 IN-3 (in), 12 IN+3 (in), 13 -V (power), 14 IN+4 (in), 15 IN-4 (in), 16 OUT4 (hiz)

## TS3V904ID
designator U?
3V Rail-to-Rail CMOS Quad Operational Amplifier (with Standby Position)
footprint SO16_N (SOIC, 16-Leads, Body 9.9x3.9mm, Pitch 1.27mm, IPC Medium Density)
footprint SO16_L (SOIC, 16-Leads, Body 9.9x3.9mm, Pitch 1.27mm, IPC High Density)
footprint SO16_M (SOIC, 16-Leads, Body 9.9x3.9mm, Pitch 1.27mm, IPC Low Density)
3D model SO16 (16-Pin Small Outline Integrated Circuit 1.27 mm Pitch)
pins: 1 OUT1 (hiz), 2 IN-1 (in), 3 IN+1 (in), 4 +V (power), 5 IN+2 (in), 6 IN-2 (in), 7 OUT2 (hiz), 8 STDBY1 (in), 9 STDBY2 (in), 10 OUT3 (hiz), 11 IN-3 (in), 12 IN+3 (in), 13 -V (power), 14 IN+4 (in), 15 IN-4 (in), 16 OUT4 (hiz)

## TS3V904IN
designator U?
3V Rail-to-Rail CMOS Quad Operational Amplifier (with Standby Position)
footprint DIP16 (DIP; 16 Leads; Row Spacing 7.62 mm; Pitch 2.54 mm)
3D model DIP16 (DIP; 16 Leads; Row Spacing 7.62 mm; Pitch 2.54 mm)
pins: 1 OUT1 (hiz), 2 IN-1 (in), 3 IN+1 (in), 4 +V (power), 5 IN+2 (in), 6 IN-2 (in), 7 OUT2 (hiz), 8 STDBY1 (in), 9 STDBY2 (in), 10 OUT3 (hiz), 11 IN-3 (in), 12 IN+3 (in), 13 -V (power), 14 IN+4 (in), 15 IN-4 (in), 16 OUT4 (hiz)

## TS3V912AID
designator U?
3V Rail-to-Rail CMOS Dual Operational Amplifier
footprint SO8_N (SOIC, 8-Leads, Body 4.9x3.9mm, Pitch 1.27mm, IPC Medium Density)
footprint SO8_L (SOIC, 8-Leads, Body 4.9x3.9mm, Pitch 1.27mm, IPC High Density)
footprint SO8_M (SOIC, 8-Leads, Body 4.9x3.9mm, Pitch 1.27mm, IPC Low Density)
3D model SO8 (8-Pin Small Outline Integrated Circuit 1.27 mm Pitch)
pins on every part: 4 V- (power), 8 V+ (power)
part A pins: 1 OUT (out), 2 IN- (in), 3 IN+ (in)
part B pins: 5 IN+ (in), 6 IN- (in), 7 OUT (out)

## TS3V912AIN
designator U?
3V Rail-to-Rail CMOS Dual Operational Amplifier
footprint DIP8 (DIP; 8 Leads; Row Spacing 7.62 mm; Pitch 2.54 mm)
3D model DIP8 (DIP; 8 Leads; Row Spacing 7.62 mm; Pitch 2.54 mm)
pins on every part: 4 V- (power), 8 V+ (power)
part A pins: 1 OUT (out), 2 IN- (in), 3 IN+ (in)
part B pins: 5 IN+ (in), 6 IN- (in), 7 OUT (out)

## TS3V912BID
designator U?
3V Rail-to-Rail CMOS Dual Operational Amplifier
footprint SO8_N (SOIC, 8-Leads, Body 4.9x3.9mm, Pitch 1.27mm, IPC Medium Density)
footprint SO8_L (SOIC, 8-Leads, Body 4.9x3.9mm, Pitch 1.27mm, IPC High Density)
footprint SO8_M (SOIC, 8-Leads, Body 4.9x3.9mm, Pitch 1.27mm, IPC Low Density)
3D model SO8 (8-Pin Small Outline Integrated Circuit 1.27 mm Pitch)
pins on every part: 4 V- (power), 8 V+ (power)
part A pins: 1 OUT (out), 2 IN- (in), 3 IN+ (in)
part B pins: 5 IN+ (in), 6 IN- (in), 7 OUT (out)

## TS3V912BIN
designator U?
3V Rail-to-Rail CMOS Dual Operational Amplifier
footprint DIP8 (DIP; 8 Leads; Row Spacing 7.62 mm; Pitch 2.54 mm)
3D model DIP8 (DIP; 8 Leads; Row Spacing 7.62 mm; Pitch 2.54 mm)
pins on every part: 4 V- (power), 8 V+ (power)
part A pins: 1 OUT (out), 2 IN- (in), 3 IN+ (in)
part B pins: 5 IN+ (in), 6 IN- (in), 7 OUT (out)

## TS3V912ID
designator U?
3V Rail-to-Rail CMOS Dual Operational Amplifier
footprint SO8_N (SOIC, 8-Leads, Body 4.9x3.9mm, Pitch 1.27mm, IPC Medium Density)
footprint SO8_L (SOIC, 8-Leads, Body 4.9x3.9mm, Pitch 1.27mm, IPC High Density)
footprint SO8_M (SOIC, 8-Leads, Body 4.9x3.9mm, Pitch 1.27mm, IPC Low Density)
3D model SO8 (8-Pin Small Outline Integrated Circuit 1.27 mm Pitch)
pins on every part: 4 V- (power), 8 V+ (power)
part A pins: 1 OUT (out), 2 IN- (in), 3 IN+ (in)
part B pins: 5 IN+ (in), 6 IN- (in), 7 OUT (out)

## TS3V912IN
designator U?
3V Rail-to-Rail CMOS Dual Operational Amplifier
footprint DIP8 (DIP; 8 Leads; Row Spacing 7.62 mm; Pitch 2.54 mm)
3D model DIP8 (DIP; 8 Leads; Row Spacing 7.62 mm; Pitch 2.54 mm)
pins on every part: 4 V- (power), 8 V+ (power)
part A pins: 1 OUT (out), 2 IN- (in), 3 IN+ (in)
part B pins: 5 IN+ (in), 6 IN- (in), 7 OUT (out)

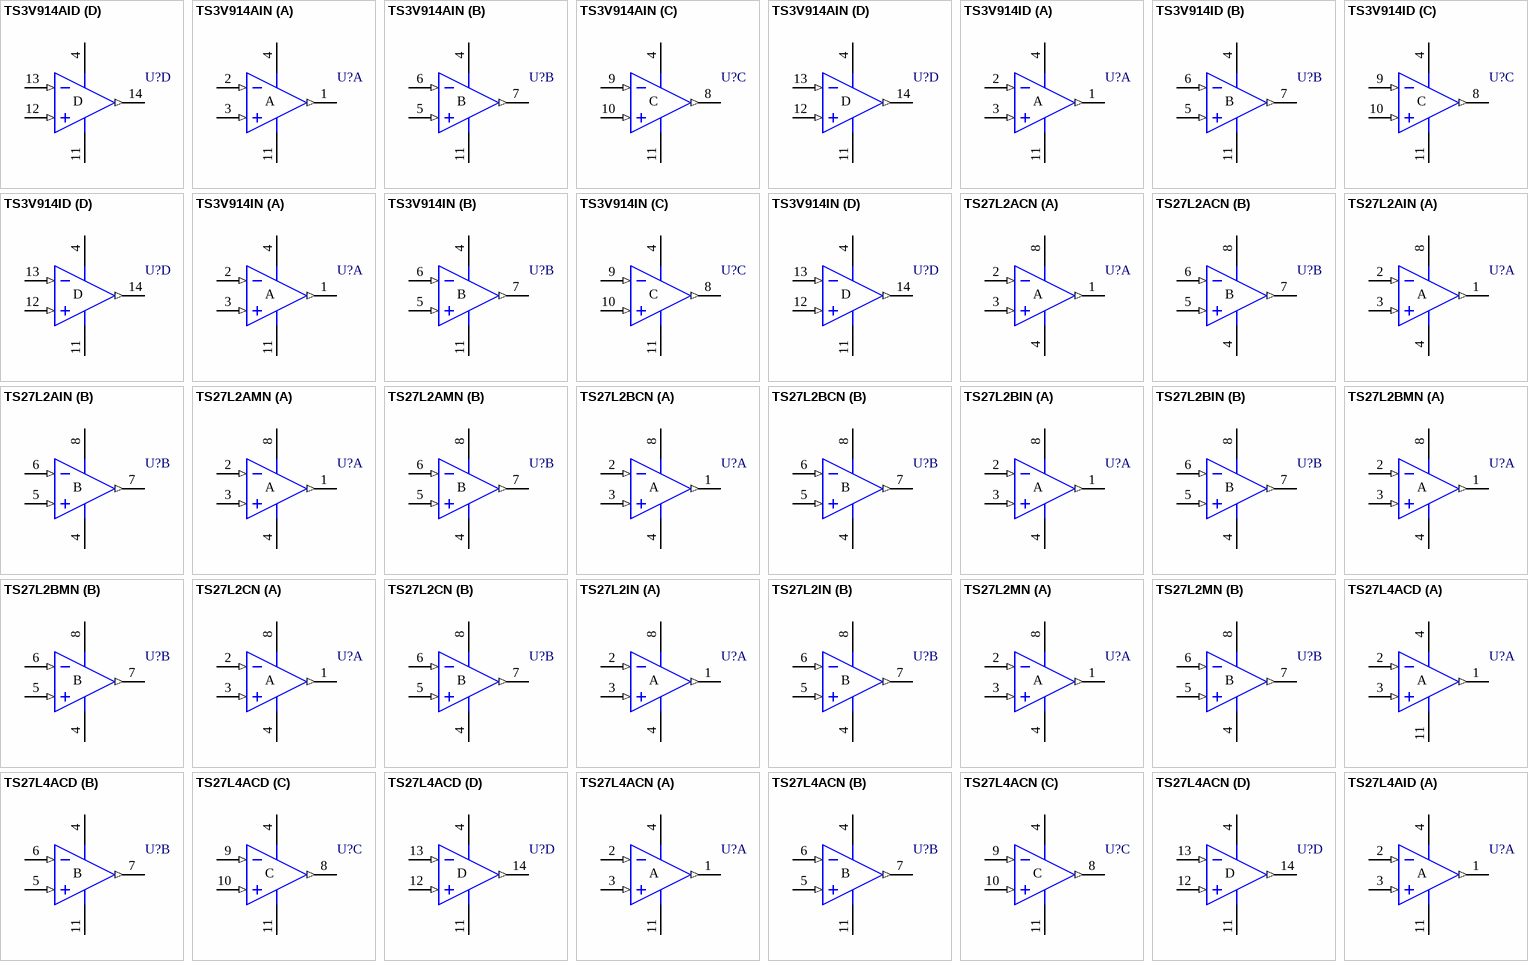
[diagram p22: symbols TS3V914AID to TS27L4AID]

## TS3V914AID
designator U?
3V Rail-to-Rail CMOS Quad Operational Amplifier
footprint SO14_N (SOIC, 14-Leads, Body 8.7x3.9mm, Pitch 1.27mm, IPC Medium Density)
footprint SO14_L (SOIC, 14-Leads, Body 8.7x3.9mm, Pitch 1.27mm, IPC High Density)
footprint SO14_M (SOIC, 14-Leads, Body 8.7x3.9mm, Pitch 1.27mm, IPC Low Density)
3D model SO14 (14-Pin Small Outline Integrated Circuit 1.27 mm Pitch)
pins on every part: 4 V+ (power), 11 V- (power)
part A pins: 1 OUT (out), 2 IN- (in), 3 IN+ (in)
part B pins: 5 IN+ (in), 6 IN- (in), 7 OUT (out)
part C pins: 8 OUT (out), 9 IN- (in), 10 IN+ (in)
part D pins: 12 IN+ (in), 13 IN- (in), 14 OUT (out)

## TS3V914AIN
designator U?
3V Rail-to-Rail CMOS Quad Operational Amplifier
footprint DIP14 (DIP; 14 Leads; Row Spacing 7.62 mm; Pitch 2.54 mm)
3D model DIP14 (DIP; 14 Leads; Row Spacing 7.62 mm; Pitch 2.54 mm)
pins on every part: 4 V+ (power), 11 V- (power)
part A pins: 1 OUT (out), 2 IN- (in), 3 IN+ (in)
part B pins: 5 IN+ (in), 6 IN- (in), 7 OUT (out)
part C pins: 8 OUT (out), 9 IN- (in), 10 IN+ (in)
part D pins: 12 IN+ (in), 13 IN- (in), 14 OUT (out)

## TS3V914ID
designator U?
3V Rail-to-Rail CMOS Quad Operational Amplifier
footprint SO14_N (SOIC, 14-Leads, Body 8.7x3.9mm, Pitch 1.27mm, IPC Medium Density)
footprint SO14_L (SOIC, 14-Leads, Body 8.7x3.9mm, Pitch 1.27mm, IPC High Density)
footprint SO14_M (SOIC, 14-Leads, Body 8.7x3.9mm, Pitch 1.27mm, IPC Low Density)
3D model SO14 (14-Pin Small Outline Integrated Circuit 1.27 mm Pitch)
pins on every part: 4 V+ (power), 11 V- (power)
part A pins: 1 OUT (out), 2 IN- (in), 3 IN+ (in)
part B pins: 5 IN+ (in), 6 IN- (in), 7 OUT (out)
part C pins: 8 OUT (out), 9 IN- (in), 10 IN+ (in)
part D pins: 12 IN+ (in), 13 IN- (in), 14 OUT (out)

## TS3V914IN
designator U?
3V Rail-to-Rail CMOS Quad Operational Amplifier
footprint DIP14 (DIP; 14 Leads; Row Spacing 7.62 mm; Pitch 2.54 mm)
3D model DIP14 (DIP; 14 Leads; Row Spacing 7.62 mm; Pitch 2.54 mm)
pins on every part: 4 V+ (power), 11 V- (power)
part A pins: 1 OUT (out), 2 IN- (in), 3 IN+ (in)
part B pins: 5 IN+ (in), 6 IN- (in), 7 OUT (out)
part C pins: 8 OUT (out), 9 IN- (in), 10 IN+ (in)
part D pins: 12 IN+ (in), 13 IN- (in), 14 OUT (out)

## TS27L2ACN
designator U?
Low-Power CMOS Dual Operational Amplifier
footprint DIP8 (DIP; 8 Leads; Row Spacing 7.62 mm; Pitch 2.54 mm)
3D model DIP8 (DIP; 8 Leads; Row Spacing 7.62 mm; Pitch 2.54 mm)
pins on every part: 4 V- (power), 8 V+ (power)
part A pins: 1 OUT (out), 2 IN- (in), 3 IN+ (in)
part B pins: 5 IN+ (in), 6 IN- (in), 7 OUT (out)

## TS27L2AIN
designator U?
Low-Power CMOS Dual Operational Amplifier
footprint DIP8 (DIP; 8 Leads; Row Spacing 7.62 mm; Pitch 2.54 mm)
3D model DIP8 (DIP; 8 Leads; Row Spacing 7.62 mm; Pitch 2.54 mm)
pins on every part: 4 V- (power), 8 V+ (power)
part A pins: 1 OUT (out), 2 IN- (in), 3 IN+ (in)
part B pins: 5 IN+ (in), 6 IN- (in), 7 OUT (out)

## TS27L2AMN
designator U?
Low-Power CMOS Dual Operational Amplifier
footprint DIP8 (DIP; 8 Leads; Row Spacing 7.62 mm; Pitch 2.54 mm)
3D model DIP8 (DIP; 8 Leads; Row Spacing 7.62 mm; Pitch 2.54 mm)
pins on every part: 4 V- (power), 8 V+ (power)
part A pins: 1 OUT (out), 2 IN- (in), 3 IN+ (in)
part B pins: 5 IN+ (in), 6 IN- (in), 7 OUT (out)

## TS27L2BCN
designator U?
Low-Power CMOS Dual Operational Amplifier
footprint DIP8 (DIP; 8 Leads; Row Spacing 7.62 mm; Pitch 2.54 mm)
3D model DIP8 (DIP; 8 Leads; Row Spacing 7.62 mm; Pitch 2.54 mm)
pins on every part: 4 V- (power), 8 V+ (power)
part A pins: 1 OUT (out), 2 IN- (in), 3 IN+ (in)
part B pins: 5 IN+ (in), 6 IN- (in), 7 OUT (out)

## TS27L2BIN
designator U?
Low-Power CMOS Dual Operational Amplifier
footprint DIP8 (DIP; 8 Leads; Row Spacing 7.62 mm; Pitch 2.54 mm)
3D model DIP8 (DIP; 8 Leads; Row Spacing 7.62 mm; Pitch 2.54 mm)
pins on every part: 4 V- (power), 8 V+ (power)
part A pins: 1 OUT (out), 2 IN- (in), 3 IN+ (in)
part B pins: 5 IN+ (in), 6 IN- (in), 7 OUT (out)

## TS27L2BMN
designator U?
Low-Power CMOS Dual Operational Amplifier
footprint DIP8 (DIP; 8 Leads; Row Spacing 7.62 mm; Pitch 2.54 mm)
3D model DIP8 (DIP; 8 Leads; Row Spacing 7.62 mm; Pitch 2.54 mm)
pins on every part: 4 V- (power), 8 V+ (power)
part A pins: 1 OUT (out), 2 IN- (in), 3 IN+ (in)
part B pins: 5 IN+ (in), 6 IN- (in), 7 OUT (out)

## TS27L2CN
designator U?
Low-Power CMOS Dual Operational Amplifier
footprint DIP8 (DIP; 8 Leads; Row Spacing 7.62 mm; Pitch 2.54 mm)
3D model DIP8 (DIP; 8 Leads; Row Spacing 7.62 mm; Pitch 2.54 mm)
pins on every part: 4 V- (power), 8 V+ (power)
part A pins: 1 OUT (out), 2 IN- (in), 3 IN+ (in)
part B pins: 5 IN+ (in), 6 IN- (in), 7 OUT (out)

## TS27L2IN
designator U?
Low-Power CMOS Dual Operational Amplifier
footprint DIP8 (DIP; 8 Leads; Row Spacing 7.62 mm; Pitch 2.54 mm)
3D model DIP8 (DIP; 8 Leads; Row Spacing 7.62 mm; Pitch 2.54 mm)
pins on every part: 4 V- (power), 8 V+ (power)
part A pins: 1 OUT (out), 2 IN- (in), 3 IN+ (in)
part B pins: 5 IN+ (in), 6 IN- (in), 7 OUT (out)

## TS27L2MN
designator U?
Low-Power CMOS Dual Operational Amplifier
footprint DIP8 (DIP; 8 Leads; Row Spacing 7.62 mm; Pitch 2.54 mm)
3D model DIP8 (DIP; 8 Leads; Row Spacing 7.62 mm; Pitch 2.54 mm)
pins on every part: 4 V- (power), 8 V+ (power)
part A pins: 1 OUT (out), 2 IN- (in), 3 IN+ (in)
part B pins: 5 IN+ (in), 6 IN- (in), 7 OUT (out)

## TS27L4ACD
designator U?
Very Low-Power CMOS Quad Operational Amplifier
footprint SO14_N (SOIC, 14-Leads, Body 8.7x3.9mm, Pitch 1.27mm, IPC Medium Density)
footprint SO14_L (SOIC, 14-Leads, Body 8.7x3.9mm, Pitch 1.27mm, IPC High Density)
footprint SO14_M (SOIC, 14-Leads, Body 8.7x3.9mm, Pitch 1.27mm, IPC Low Density)
3D model SO14 (14-Pin Small Outline Integrated Circuit 1.27 mm Pitch)
pins on every part: 4 V+ (power), 11 V- (power)
part A pins: 1 OUT (out), 2 IN- (in), 3 IN+ (in)
part B pins: 5 IN+ (in), 6 IN- (in), 7 OUT (out)
part C pins: 8 OUT (out), 9 IN- (in), 10 IN+ (in)
part D pins: 12 IN+ (in), 13 IN- (in), 14 OUT (out)

## TS27L4ACN
designator U?
Very Low-Power CMOS Quad Operational Amplifier
footprint DIP14 (DIP; 14 Leads; Row Spacing 7.62 mm; Pitch 2.54 mm)
3D model DIP14 (DIP; 14 Leads; Row Spacing 7.62 mm; Pitch 2.54 mm)
pins on every part: 4 V+ (power), 11 V- (power)
part A pins: 1 OUT (out), 2 IN- (in), 3 IN+ (in)
part B pins: 5 IN+ (in), 6 IN- (in), 7 OUT (out)
part C pins: 8 OUT (out), 9 IN- (in), 10 IN+ (in)
part D pins: 12 IN+ (in), 13 IN- (in), 14 OUT (out)

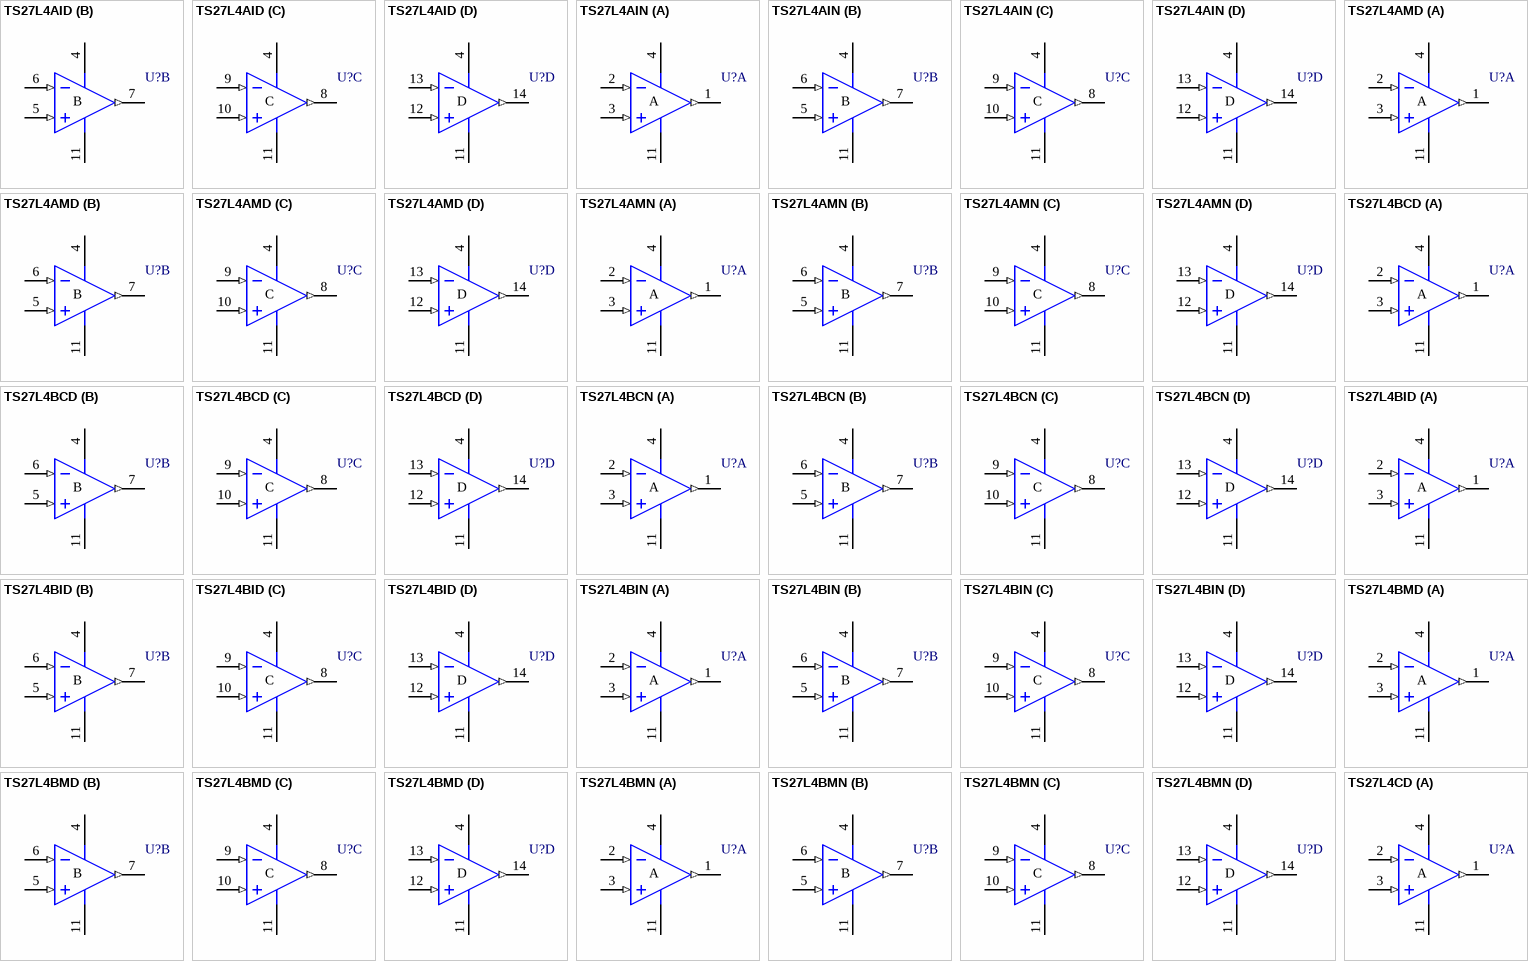
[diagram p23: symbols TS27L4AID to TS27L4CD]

## TS27L4AID
designator U?
Very Low-Power CMOS Quad Operational Amplifier
footprint SO14_N (SOIC, 14-Leads, Body 8.7x3.9mm, Pitch 1.27mm, IPC Medium Density)
footprint SO14_L (SOIC, 14-Leads, Body 8.7x3.9mm, Pitch 1.27mm, IPC High Density)
footprint SO14_M (SOIC, 14-Leads, Body 8.7x3.9mm, Pitch 1.27mm, IPC Low Density)
3D model SO14 (14-Pin Small Outline Integrated Circuit 1.27 mm Pitch)
pins on every part: 4 V+ (power), 11 V- (power)
part A pins: 1 OUT (out), 2 IN- (in), 3 IN+ (in)
part B pins: 5 IN+ (in), 6 IN- (in), 7 OUT (out)
part C pins: 8 OUT (out), 9 IN- (in), 10 IN+ (in)
part D pins: 12 IN+ (in), 13 IN- (in), 14 OUT (out)

## TS27L4AIN
designator U?
Very Low-Power CMOS Quad Operational Amplifier
footprint DIP14 (DIP; 14 Leads; Row Spacing 7.62 mm; Pitch 2.54 mm)
3D model DIP14 (DIP; 14 Leads; Row Spacing 7.62 mm; Pitch 2.54 mm)
pins on every part: 4 V+ (power), 11 V- (power)
part A pins: 1 OUT (out), 2 IN- (in), 3 IN+ (in)
part B pins: 5 IN+ (in), 6 IN- (in), 7 OUT (out)
part C pins: 8 OUT (out), 9 IN- (in), 10 IN+ (in)
part D pins: 12 IN+ (in), 13 IN- (in), 14 OUT (out)

## TS27L4AMD
designator U?
Very Low-Power CMOS Quad Operational Amplifier
footprint SO14_N (SOIC, 14-Leads, Body 8.7x3.9mm, Pitch 1.27mm, IPC Medium Density)
footprint SO14_L (SOIC, 14-Leads, Body 8.7x3.9mm, Pitch 1.27mm, IPC High Density)
footprint SO14_M (SOIC, 14-Leads, Body 8.7x3.9mm, Pitch 1.27mm, IPC Low Density)
3D model SO14 (14-Pin Small Outline Integrated Circuit 1.27 mm Pitch)
pins on every part: 4 V+ (power), 11 V- (power)
part A pins: 1 OUT (out), 2 IN- (in), 3 IN+ (in)
part B pins: 5 IN+ (in), 6 IN- (in), 7 OUT (out)
part C pins: 8 OUT (out), 9 IN- (in), 10 IN+ (in)
part D pins: 12 IN+ (in), 13 IN- (in), 14 OUT (out)

## TS27L4AMN
designator U?
Very Low-Power CMOS Quad Operational Amplifier
footprint DIP14 (DIP; 14 Leads; Row Spacing 7.62 mm; Pitch 2.54 mm)
3D model DIP14 (DIP; 14 Leads; Row Spacing 7.62 mm; Pitch 2.54 mm)
pins on every part: 4 V+ (power), 11 V- (power)
part A pins: 1 OUT (out), 2 IN- (in), 3 IN+ (in)
part B pins: 5 IN+ (in), 6 IN- (in), 7 OUT (out)
part C pins: 8 OUT (out), 9 IN- (in), 10 IN+ (in)
part D pins: 12 IN+ (in), 13 IN- (in), 14 OUT (out)

## TS27L4BCD
designator U?
Very Low-Power CMOS Quad Operational Amplifier
footprint SO14_N (SOIC, 14-Leads, Body 8.7x3.9mm, Pitch 1.27mm, IPC Medium Density)
footprint SO14_L (SOIC, 14-Leads, Body 8.7x3.9mm, Pitch 1.27mm, IPC High Density)
footprint SO14_M (SOIC, 14-Leads, Body 8.7x3.9mm, Pitch 1.27mm, IPC Low Density)
3D model SO14 (14-Pin Small Outline Integrated Circuit 1.27 mm Pitch)
pins on every part: 4 V+ (power), 11 V- (power)
part A pins: 1 OUT (out), 2 IN- (in), 3 IN+ (in)
part B pins: 5 IN+ (in), 6 IN- (in), 7 OUT (out)
part C pins: 8 OUT (out), 9 IN- (in), 10 IN+ (in)
part D pins: 12 IN+ (in), 13 IN- (in), 14 OUT (out)

## TS27L4BCN
designator U?
Very Low-Power CMOS Quad Operational Amplifier
footprint DIP14 (DIP; 14 Leads; Row Spacing 7.62 mm; Pitch 2.54 mm)
3D model DIP14 (DIP; 14 Leads; Row Spacing 7.62 mm; Pitch 2.54 mm)
pins on every part: 4 V+ (power), 11 V- (power)
part A pins: 1 OUT (out), 2 IN- (in), 3 IN+ (in)
part B pins: 5 IN+ (in), 6 IN- (in), 7 OUT (out)
part C pins: 8 OUT (out), 9 IN- (in), 10 IN+ (in)
part D pins: 12 IN+ (in), 13 IN- (in), 14 OUT (out)

## TS27L4BID
designator U?
Very Low-Power CMOS Quad Operational Amplifier
footprint SO14_N (SOIC, 14-Leads, Body 8.7x3.9mm, Pitch 1.27mm, IPC Medium Density)
footprint SO14_L (SOIC, 14-Leads, Body 8.7x3.9mm, Pitch 1.27mm, IPC High Density)
footprint SO14_M (SOIC, 14-Leads, Body 8.7x3.9mm, Pitch 1.27mm, IPC Low Density)
3D model SO14 (14-Pin Small Outline Integrated Circuit 1.27 mm Pitch)
pins on every part: 4 V+ (power), 11 V- (power)
part A pins: 1 OUT (out), 2 IN- (in), 3 IN+ (in)
part B pins: 5 IN+ (in), 6 IN- (in), 7 OUT (out)
part C pins: 8 OUT (out), 9 IN- (in), 10 IN+ (in)
part D pins: 12 IN+ (in), 13 IN- (in), 14 OUT (out)

## TS27L4BIN
designator U?
Very Low-Power CMOS Quad Operational Amplifier
footprint DIP14 (DIP; 14 Leads; Row Spacing 7.62 mm; Pitch 2.54 mm)
3D model DIP14 (DIP; 14 Leads; Row Spacing 7.62 mm; Pitch 2.54 mm)
pins on every part: 4 V+ (power), 11 V- (power)
part A pins: 1 OUT (out), 2 IN- (in), 3 IN+ (in)
part B pins: 5 IN+ (in), 6 IN- (in), 7 OUT (out)
part C pins: 8 OUT (out), 9 IN- (in), 10 IN+ (in)
part D pins: 12 IN+ (in), 13 IN- (in), 14 OUT (out)

## TS27L4BMD
designator U?
Very Low-Power CMOS Quad Operational Amplifier
footprint SO14_N (SOIC, 14-Leads, Body 8.7x3.9mm, Pitch 1.27mm, IPC Medium Density)
footprint SO14_L (SOIC, 14-Leads, Body 8.7x3.9mm, Pitch 1.27mm, IPC High Density)
footprint SO14_M (SOIC, 14-Leads, Body 8.7x3.9mm, Pitch 1.27mm, IPC Low Density)
3D model SO14 (14-Pin Small Outline Integrated Circuit 1.27 mm Pitch)
pins on every part: 4 V+ (power), 11 V- (power)
part A pins: 1 OUT (out), 2 IN- (in), 3 IN+ (in)
part B pins: 5 IN+ (in), 6 IN- (in), 7 OUT (out)
part C pins: 8 OUT (out), 9 IN- (in), 10 IN+ (in)
part D pins: 12 IN+ (in), 13 IN- (in), 14 OUT (out)

## TS27L4BMN
designator U?
Very Low-Power CMOS Quad Operational Amplifier
footprint DIP14 (DIP; 14 Leads; Row Spacing 7.62 mm; Pitch 2.54 mm)
3D model DIP14 (DIP; 14 Leads; Row Spacing 7.62 mm; Pitch 2.54 mm)
pins on every part: 4 V+ (power), 11 V- (power)
part A pins: 1 OUT (out), 2 IN- (in), 3 IN+ (in)
part B pins: 5 IN+ (in), 6 IN- (in), 7 OUT (out)
part C pins: 8 OUT (out), 9 IN- (in), 10 IN+ (in)
part D pins: 12 IN+ (in), 13 IN- (in), 14 OUT (out)

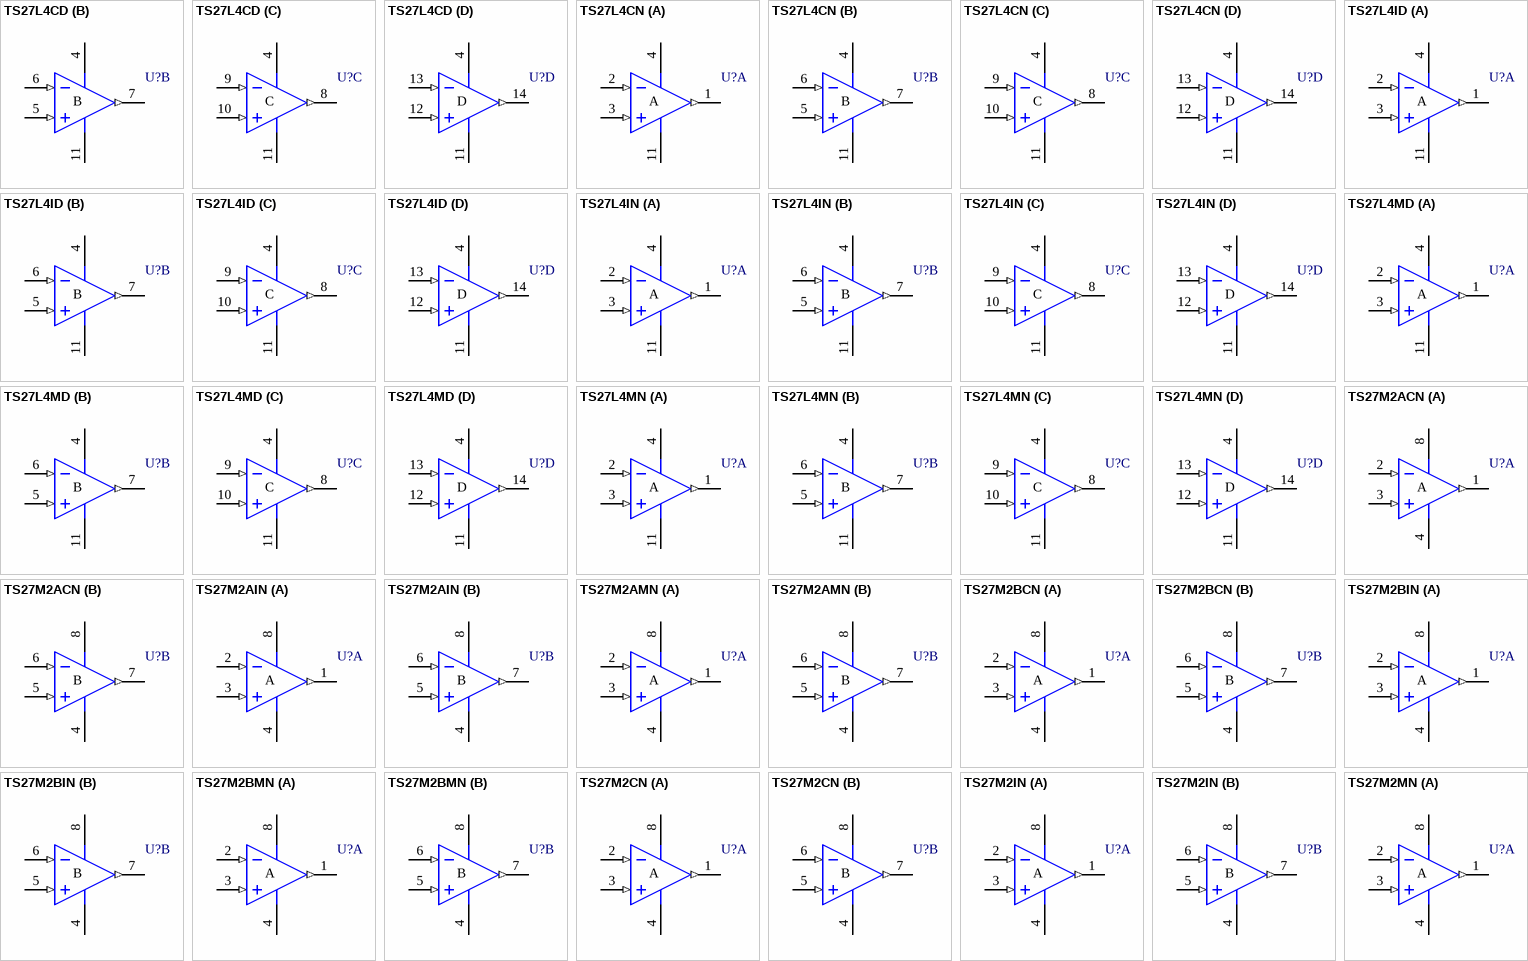
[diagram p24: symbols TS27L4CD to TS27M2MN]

## TS27L4CD
designator U?
Very Low-Power CMOS Quad Operational Amplifier
footprint SO14_N (SOIC, 14-Leads, Body 8.7x3.9mm, Pitch 1.27mm, IPC Medium Density)
footprint SO14_L (SOIC, 14-Leads, Body 8.7x3.9mm, Pitch 1.27mm, IPC High Density)
footprint SO14_M (SOIC, 14-Leads, Body 8.7x3.9mm, Pitch 1.27mm, IPC Low Density)
3D model SO14 (14-Pin Small Outline Integrated Circuit 1.27 mm Pitch)
pins on every part: 4 V+ (power), 11 V- (power)
part A pins: 1 OUT (out), 2 IN- (in), 3 IN+ (in)
part B pins: 5 IN+ (in), 6 IN- (in), 7 OUT (out)
part C pins: 8 OUT (out), 9 IN- (in), 10 IN+ (in)
part D pins: 12 IN+ (in), 13 IN- (in), 14 OUT (out)

## TS27L4CN
designator U?
Very Low-Power CMOS Quad Operational Amplifier
footprint DIP14 (DIP; 14 Leads; Row Spacing 7.62 mm; Pitch 2.54 mm)
3D model DIP14 (DIP; 14 Leads; Row Spacing 7.62 mm; Pitch 2.54 mm)
pins on every part: 4 V+ (power), 11 V- (power)
part A pins: 1 OUT (out), 2 IN- (in), 3 IN+ (in)
part B pins: 5 IN+ (in), 6 IN- (in), 7 OUT (out)
part C pins: 8 OUT (out), 9 IN- (in), 10 IN+ (in)
part D pins: 12 IN+ (in), 13 IN- (in), 14 OUT (out)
